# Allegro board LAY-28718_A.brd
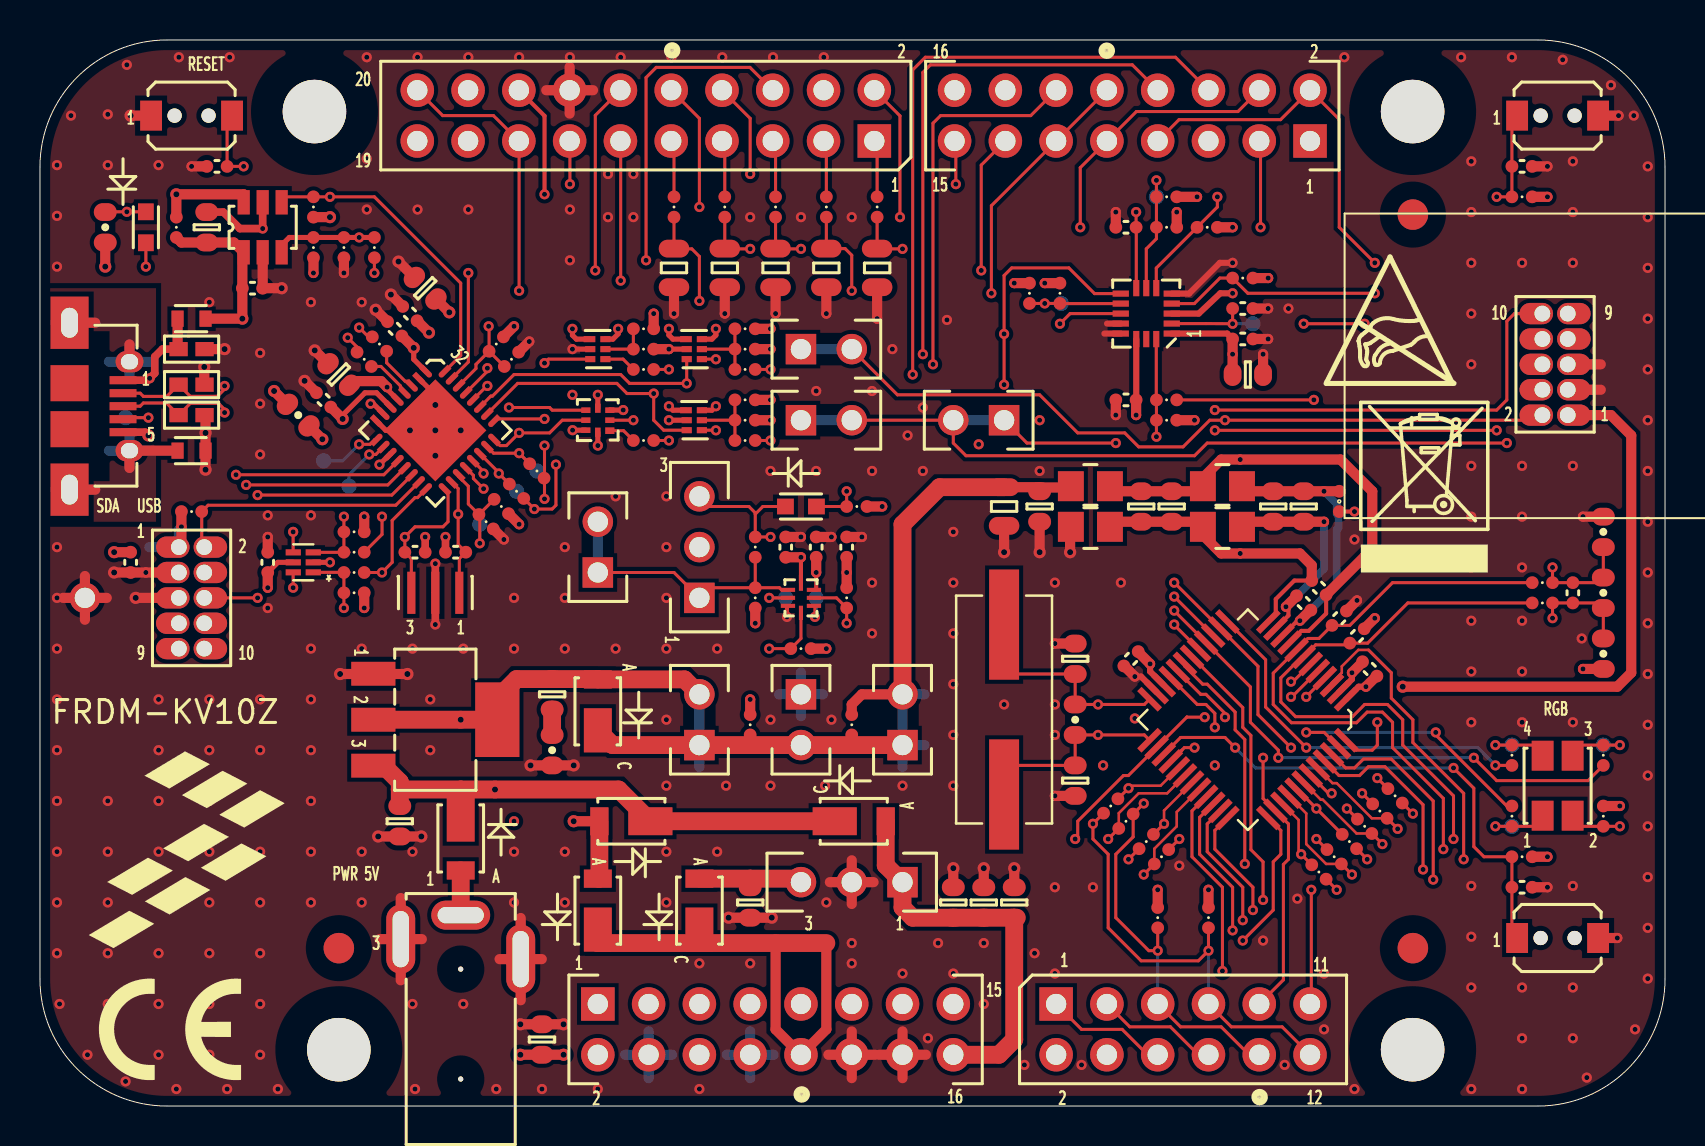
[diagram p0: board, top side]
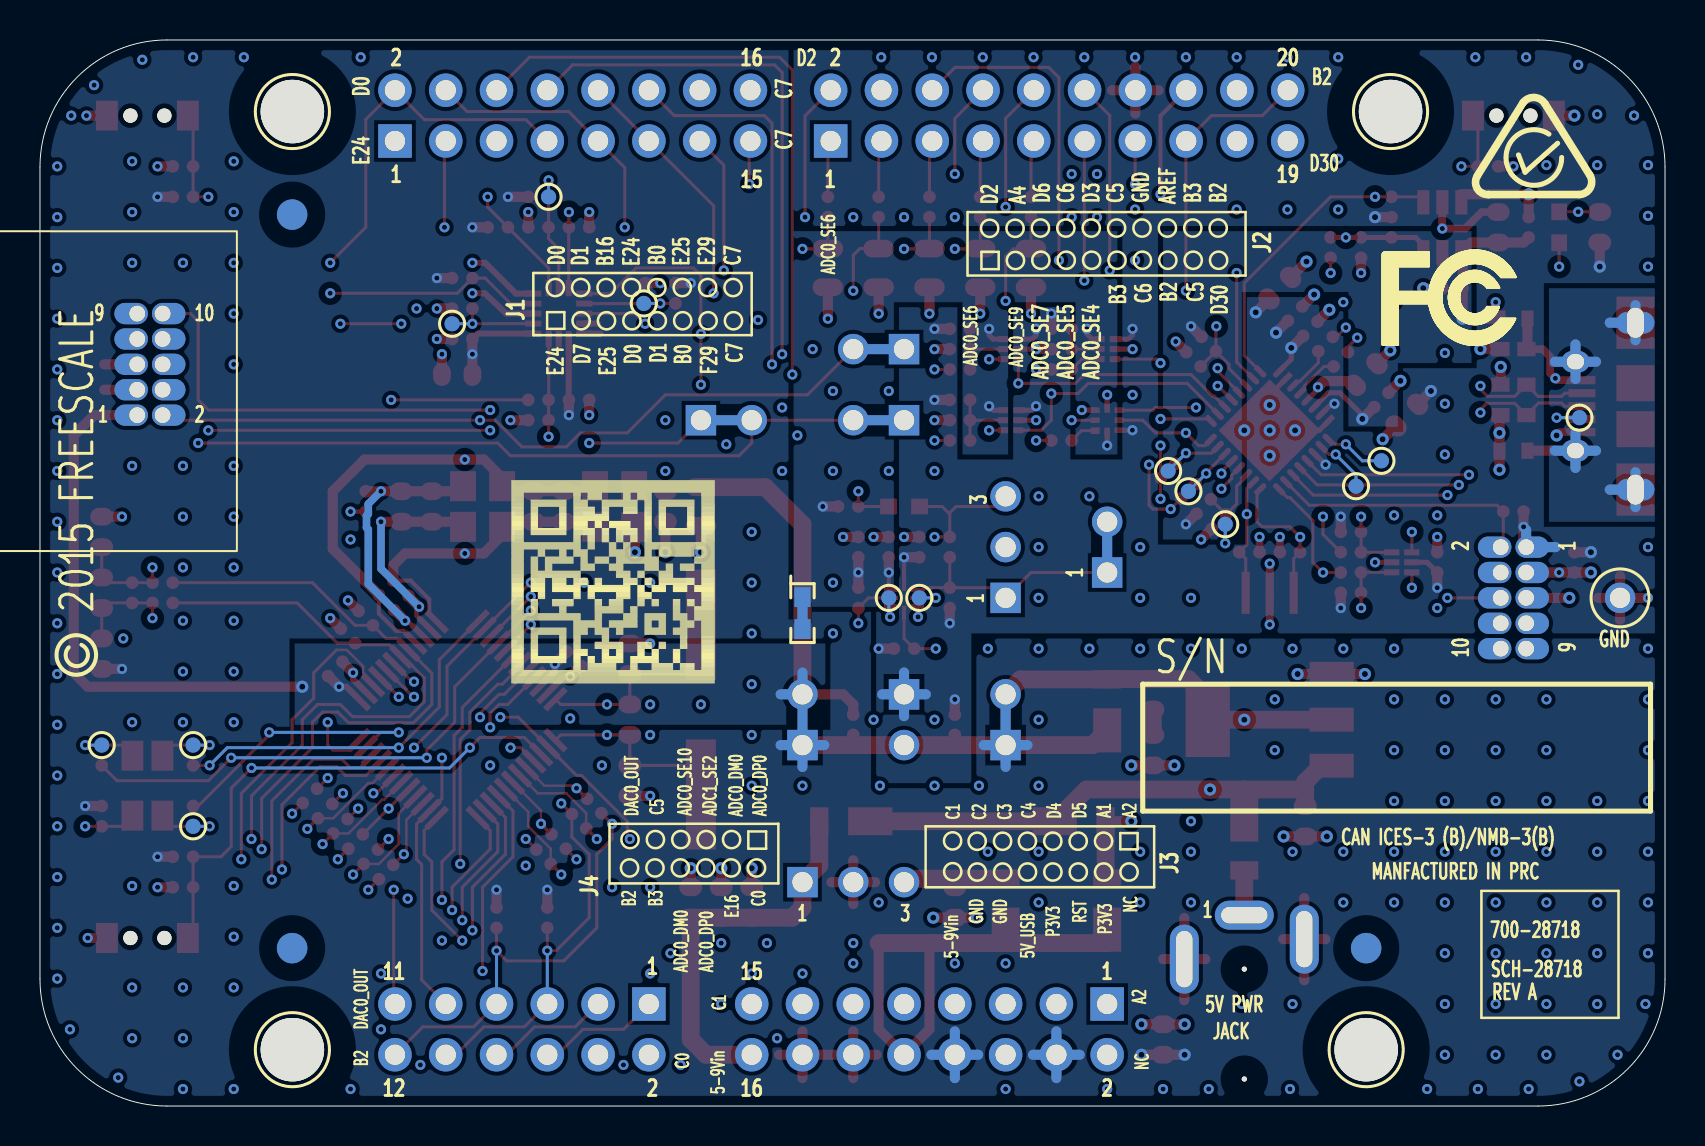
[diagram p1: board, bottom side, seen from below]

Outline 81.28 x 53.34 mm; copper layers: TOP, GND, INT_1, BOTTOM. Coordinates in mm from the lower left corner of the outline.
Outline path: 0,46.99 arc(1.86,51.48) 6.35,53.34 74.93,53.34 arc(79.42,51.48) 81.28,46.99 81.28,6.35 arc(79.42,1.86) 74.93,0 6.35,0 arc(1.86,1.86) 0,6.35 0,46.99

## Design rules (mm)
net group LEDRGB_BLUE: nets LEDRGB_BLUE PTE25
net group USB_SI_CONN_D: nets SDA_USB_CONN_DN SDA_USB_CONN_DP
net group USB_SI_D: nets SDA_USB_DN SDA_USB_DP

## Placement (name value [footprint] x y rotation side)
C1  10uF  [CC0402_25]  14.19 35.33 135 top
C2  1000pF  [CC0402_25]  8.85 47.02 180 top
C3  0.1UF  [CC0402_25]  60.16 39.9 0 top
C4  0.1UF  [CC0402_25]  60.16 38.38 0 top
C5  4.7uF  [CC0603_OV]  60.41 36.6 0 top
C6  22PF  [CC0402_25]  20.79 27.71 180 top
C7  0.1UF  [CC0402_25]  38.82 27.97 90 top
C8  0.1UF  [CC0402_25]  11.39 27.2 90 top
C9  22PF  [CC0402_25]  18.76 27.71 0 top
C10  0.1UF  [CC0402_25]  17.74 38.89 135 top
C11  2.2UF  [CC0603_OV]  14.95 36.6 135 top
C12  1.0UF  [CC0402_25]  18.5 39.65 135 top
C13  0.1UF  [CC0402_25]  54.32 43.97 180 top
C14  0.1UF  [CC0402_25]  54.32 35.33 180 top
C15  10uF  [CC0603_OV]  19.27 40.92 135 top
C16  0.1UF  [CC0402_25]  10.63 40.92 0 top
C17  4.7uF  [CC0402_25]  37.3 27.97 90 top
C18  0.1UF  [CC0402_25]  4.53 27.2 270 top
C19  18PF  [CC0603_OV]  8.34 43.97 90 top
C20  18PF  [CC0603_OV]  51.78 16.28 90 top
C21  0.1UF  [CC0402_25]  76.67 25.68 90 top
C22  2200PF  [CC0402_25]  65.87 23.52 45 top
C23  4.7uF  [CC0402_25]  40.35 27.97 90 top
C24  18PF  [CC0603_OV]  51.78 22.38 270 top
C29  0.1UF  [CC0402_25]  63.21 25.17 135 top
C30  0.1UF  [CC0402_25]  63.97 25.93 135 top
C31  0.1UF  [CC0402_25]  54.57 22.38 225 top
C32  0.1UF  [CC0402_25]  66.51 21.87 135 top
C33  0.1UF  [CC0603_OV]  50 30 270 top
C34  10UF  [CC0805_OV]  48.22 30 270 top
C35  2200PF  [CC0402_25]  64.99 24.41 45 top
C36  0.1UF  [CC0603_OV]  55.08 30 270 top
C39  0.1UF  [CC0603_OV]  56.6 30 270 top
C40  2.2UF  [CC0603_OV]  25.11 3.33 90 top
C41  10uF  [CC0603_OV]  18 14.25 270 top
C42  0.1UF  [CC0603_OV]  61.68 30 270 top
C43  0.1UF  [CC0603_OV]  63.21 30 270 top
C44  220PF  [CC0805_OV]  36.79 41.94 270 top
C50  10uF  [CC0603_OV]  48.73 10.19 90 top
C51  10uF  [CC0603_OV]  25.62 20.6 270 top
C52  10uF  [CC0603_OV]  47.21 10.19 90 top
C53  10uF  [CC0603_OV]  35.52 10.19 270 top
C54  10uF  [CC0603_OV]  45.68 10.19 90 top
C55  0.1UF  [CC0402_25]  74.13 10.95 0 top
C56  0.1UF  [CC0402_25]  74.13 47.02 0 top
C505  220PF  [CC0805_OV]  41.87 41.94 270 top
C507  220PF  [CC0805_OV]  34.25 41.94 270 top
C516  220PF  [CC0805_OV]  39.33 41.94 270 top
C522  220PF  [CC0805_OV]  31.71 41.94 270 top
D1  RED  [LED_0603]  38.06 30 180 top
D2  LED GREEN  [LED_0603]  5.3 43.97 270 top
D4  CLV1A-FKB-CJ1M1F1BB7R4S3  [LED4_3P4X3MM_SMT]  75.91 16.03 180 top
D5  DFLS130L-7  [POWERDI-123_3MMX2MM]  27.9 9.68 90 top
D6  DFLS130L-7  [POWERDI-123_3MMX2MM]  29.68 14.25 180 top
D9  DFLS130L-7  [POWERDI-123_3MMX2MM]  21.04 13.49 270 top
D10  DFLS130L-7  [POWERDI-123_3MMX2MM]  40.6 14.25 0 top
D11  DFLS130L-7  [POWERDI-123_3MMX2MM]  27.9 19.65 90 top
D13  DFLS130L-7  [POWERDI-123_3MMX2MM]  32.98 9.68 90 top
J1  CON_2X8  [HDR208_ESQ_SKT]  63.53 48.29 270 top
J2  CON_2x10  [HDR210_ESQ_SKT]  41.73 48.29 270 top
J3  CON_2X8  [HDR208_ESQ_SKT]  27.9 5.11 90 top
J4  CON_2X6  [HDR206_ESQ_SKT]  50.83 5.11 90 top
J5  HDR 1X2 TH  [SH_HDR102_BOTTOM]  27.9 26.7 180 top
J6  MICRO USB AB 5  [CON5_MICROUSB]  1.48 35.02 270 top
J8  HDR 1X2 TH  [SH_HDR102_BOTTOM]  38.06 34.32 90 top
J9  HDR 2X5  [HDR_5X2_FTSH_TH_NSP]  76.42 34.57 180 top
J10  HDR 2X5  [HDR_5X2_FTSH_TH_NSP]  6.95 27.97 0 top
J11  HDR 1X2 TH  [SH_HDR102_BOTTOM]  48.22 34.32 270 top
J12  HDR 1X2 TH  [SH_HDR102_BOTTOM]  38.06 37.87 90 top
J18  HDR 1X2  [HDR102]  38.06 20.6 0 top
J19  HDR 1X2 TH  [SH_HDR102_BOTTOM]  32.98 18.06 180 top
J20  HDR 1X2 TH  [SH_HDR102_BOTTOM]  43.14 18.06 180 top
J24  CON PWR 3  [CON_JACK_PJ1_022_TH-RA]  21.04 9.55 90 top
J25  HDR_1X3  [HDR103]  32.98 25.43 180 top
J27  HDR_1X3  [HDR103]  43.14 11.2 270 top
L1  330 OHM  [IND_1608]  7.58 32.79 0 top
L2  330 OHM  [IND_1608]  7.58 39.4 0 top
L3  1000@100MHZ  [IND_0805]  52.54 31.01 180 top
L8  1000@100MHZ  [IND_0805]  52.54 28.98 180 top
L9  1000@100MHZ  [IND_0805]  59.14 31.01 180 top
L10  1000@100MHZ  [IND_0805]  59.14 28.98 180 top
NOREF  -  []  66.07 28.85 0 top
NOREF#2  -  []  -239.61 -215.75 0 top
NOREF#3  -  []  -381.97 185.27 0 top
NOREF#4  -  []  -16.59 -36.7 0 top
NOREF#5  -  []  12.88 1.39 0 top
NOREF#6  -  []  2.44 7.9 0 top
NOREF#7  -  []  2.95 1.3 0 top
NOREF#8  -  []  0 41.47 0 top
NOREF#9  -  [unnamed#2]  68.67 7.9 0 top
NOREF#10  -  [unnamed#2]  14.95 7.9 0 top
NOREF#11  -  []  79.64 51.25 0 top
NOREF#12  -  []  64.35 36.16 0 top
NOREF#13  -  []  -408 -339.88 0 top
NOREF#14  -  [unnamed#2]  68.67 44.6 0 top
NOREF#15  -  []  192.91 64.47 0 top
NOREF#16  -  []  13.74 2.72 0 top
NOREF#17  -  []  70.32 0.01 90 top
NOREF#18  -  []  13.74 2.72 0 top
NOREF#19  -  [unnamed#2]  14.95 7.9 180 bottom
NOREF#20  -  [unnamed#2]  68.66 49.76 180 bottom
NOREF#21  -  []  6.57 47.46 180 bottom
NOREF#22  -  [unnamed#2]  13.73 49.76 180 bottom
NOREF#23  -  []  52.6 26.25 180 bottom
NOREF#24  -  [unnamed#2]  68.66 2.82 180 bottom
NOREF#25  -  [unnamed#2]  14.95 2.82 180 bottom
NOREF#26  -  []  26.12 14.76 180 bottom
NOREF#27  -  [unnamed#2]  68.67 44.6 180 bottom
NOREF#28  -  [unnamed#2]  68.67 7.9 180 bottom
NOREF#29  -  []  79.59 22.69 90 bottom
QZ1  10MHZ  [XTAL2-216X60-HCM49]  48.22 19.84 90 top
R1  10.0K  [RC0402_25]  74.13 45.49 180 top
R2  100  [RC0402_25]  40.86 30 180 top
R3  0  [RC0402_25]  24.85 31.78 135 top
R4  4.7K  [RC0402_25]  38.06 22.89 0 top
R5  4.7K  [RC0402_25]  23.08 30 135 top
R6  10.0K  [RC0402_25]  22.31 29.24 315 top
R7  10.0K  [RC0402_25]  23.58 37.36 45 top
R8  4.7K  [RC0402_25]  22.82 38.13 225 top
R9  10.0K  [RC0402_25]  60.16 41.43 180 top
R10  0  [RC0402_25]  35.78 27.97 90 top
R11  180K  [RC0402_25]  40.35 25.43 270 top
R12  4.7K  [RC0402_25]  35.27 35.33 180 top
R13  10.0K  [RC0402_25]  35.27 34.32 0 top
R14  10.0K  [RC0402_25]  35.78 25.43 90 top
R15  10.0K  [RC0402_25]  58.38 43.97 180 top
R16  10.0K  [RC0402_25]  30.19 37.87 0 top
R17  220  [RC0603_OV]  3.26 43.97 90 top
R18  0  [RC0402_25]  23.84 30.76 135 top
R19  0  [RC0402_25]  35.27 33.3 180 top
R20  33  [RC0402_25]  16.98 38.13 315 top
R21  10.0K  [RC0402_25]  7.58 29.74 0 top
R22  33  [RC0402_25]  16.22 37.36 315 top
R23  4.7K  [RC0402_25]  30.19 38.89 180 top
R24  0  [RC0402_25]  30.19 36.86 0 top
R25  0  [RC0402_25]  15.71 26.7 0 top
R26  10.0K  [RC0402_25]  15.71 25.68 180 top
R27  10.0K  [RC0402_25]  15.71 28.73 0 top
R28  0  [RC0402_25]  15.71 27.71 0 top
R29  1.0K  [RC0402_25]  16.73 42.95 90 top
R30  15K  [RC0402_25]  15.2 42.95 270 top
R31  10.0K  [RC0402_25]  56.35 43.97 0 top
R32  10.0K  [RC0402_25]  56.35 45.49 180 top
R33  0  [RC0402_25]  35.27 36.86 180 top
R34  10.0K  [RC0402_25]  13.68 42.95 90 top
R35  10.0K  [RC0402_25]  13.68 44.98 90 top
R36  0  [RC0603_OV]  12.92 34.57 315 top
R37  4.7K  [RC0402_25]  35.27 38.89 180 top
R38  0  [RC0402_25]  30.19 33.3 0 top
R39  10.0K  [RC0402_25]  35.27 37.87 0 top
R40  10.0K  [RC0402_25]  49.49 40.67 270 top
R41  0  [RC0402_25]  6.82 43.97 270 top
R42  10.0K  [RC0402_25]  56.35 34.32 0 top
R43  10.0K  [RC0402_25]  51.02 40.67 90 top
R44  4.99K  [RC0603_OV]  78.19 28.73 90 top
R45  4.99K  [RC0603_OV]  78.19 22.63 90 top
R46  100  [RC0402_25]  75.15 26.19 0 top
R47  100  [RC0402_25]  75.15 25.17 0 top
R48  4.99K  [RC0603_OV]  25.62 17.81 270 top
R49  10.0K  [RC0402_25]  55.91 9.42 270 top
R50  10.0K  [RC0402_25]  58.45 9.42 270 top
R52  1.0M  [RC0603_OV]  51.78 19.33 270 top
R53  0  [RC0402_25]  64.99 30.25 270 top
R54  0  [RC0402_25]  55.33 13.23 225 top
R55  0  [RC0402_25]  56.1 12.47 225 top
R58  0  [RC0402_25]  65.49 13.23 135 top
R59  0  [RC0402_25]  66.26 14 135 top
R60  0  [RC0402_25]  63.97 11.71 135 top
R61  0  [RC0402_25]  35.52 19.08 90 top
R62  0  [RC0402_25]  64.73 12.47 135 top
R63  10  [RC0402_25]  40.6 19.08 90 top
R64  0  [RC0402_25]  56.35 35.33 0 top
R65  0  [RC0402_25]  53.56 15.01 225 top
R66  0  [RC0402_25]  54.32 14.25 225 top
R67  0  [RC0402_25]  67.78 15.52 135 top
R68  0  [RC0402_25]  67.02 14.76 135 top
R69  576  [RC0402_25]  73.62 14.5 270 top
R73  270  [RC0402_25]  78.19 17.55 270 top
R74  270  [RC0402_25]  73.62 17.55 270 top
R75  10.0K  [RC0402_25]  74.13 12.47 180 top
R76  100  [RC0402_25]  36.79 44.98 90 top
R88  130  [RC0402_25]  78.19 14.5 270 top
R534  100  [RC0402_25]  41.87 44.98 90 top
R549  100  [RC0402_25]  39.33 44.98 90 top
R551  100  [RC0402_25]  34.25 44.98 90 top
R555  100  [RC0402_25]  31.71 44.98 90 top
RT1  10K  [RC0603_OV]  78.19 25.68 90 top
SH1  0  [SH0603]  43.14 24.66 270 bottom
SW1  SW2_STM151XX  [SW2_4X3MM_SM]  7.58 49.56 0 top
SW2  SW2_STM151XX  [SW2_4X3MM_SM]  75.91 49.56 0 top
SW3  SW2_STM151XX  [SW2_4X3MM_SM]  75.91 8.41 0 top
TP1  -  [TPAD_030]  24.85 31.78 180 bottom
TP2  -  [TPAD_030]  38.82 25.43 90 bottom
TP3  -  [TPAD_030]  37.3 25.43 90 bottom
TP4  -  [TPAD_030]  60.67 39.14 45 bottom
TP5  -  [TPAD_030]  22 29.11 180 bottom
TP6  -  [TPAD_030]  23.84 30.76 180 bottom
TP7  -  [TPAD_030]  4.28 34.44 180 bottom
TP8  -  [TPAD_030]  55.84 45.49 315 bottom
TP9  -  [TPAD_030]  15.46 31.01 180 bottom
TP10  -  [TPAD_030]  14.19 32.28 180 bottom
TP11  -  [TPAD_030]  51.08 40.16 45 bottom
TP13  -  [TPAD_030]  73.62 14 270 bottom
TP14  -  [TPAD_030]  78.19 18.06 270 bottom
TP16  TEST POINT WHITE  [TEST_LOOP]  2.25 25.43 180 bottom
TP17  -  [TPAD_030]  73.62 18.06 270 bottom
U1  0402ESDA-MLP  [0402_MLP]  7.58 37.87 0 top
U2  74LVCH1T45  [UDFN6_1X1P5MM]  32.73 34.32 0 top
U3  NTSX2102GU8H  [XQFN8_1P45X1P25MM]  38.06 25.43 270 top
U4  0402ESDA-MLP  [0402_MLP]  7.58 36.09 0 top
U5  MK20DX128VFM5  [QFN32_S142EP]  19.77 33.81 315 top
U6  0402ESDA-MLP  [0402_MLP]  7.58 34.57 0 top
U7  74LVCH1T45  [UDFN6_1X1P5MM]  27.9 37.87 0 top
U8  FXOS8700CQ  [QFN5X3_0P5_3X3]  55.33 39.65 180 top
U9  NLX2G14  [UDFN6_1P45X1_0P5MM]  13.17 27.2 180 top
U10  74LVC2T45GM,125  [QFN8_1P6X1P6MM]  27.9 34.32 180 top
U11  MIC2005-0.8YM6  [SOT23-6_A]  11.14 43.97 90 top
U12  74LVCH1T45  [UDFN6_1X1P5MM]  32.73 37.87 0 top
U13  MKV10Z32VLF7  [QFP50P900X900X160-48N]  60.41 19.33 225 top
U17  NCP1117ST33T3G  [SOT223]  19.77 19.33 270 top
Y1  8.00MHZ  [XTAL3_3P35X1P45_SM]  19.77 25.68 0 top

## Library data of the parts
C1-C6 C9 C11-C14 C21 C22 C29-C32 C35 C40 C41 C44 C50-C56 C505 C507 C516 C522 = CAP_NP
C7 C8 C10 C15-C18 C23 C33 C34 C36 C39 C42 C43 = CAP_NP: tolerance: 10%
C19 C20 C24 = CAP_NP: tolerance: 5%
D1 D2 = LED
D4 = CLV1A_LED_4P
D5 D6 D9-D11 D13 = DIODE_SCHTKY
J1 J3 = CONN_HDR_8X2
J2 = CONN_HDR_10X2
J4 = CONN_HDR_6X2
J5 J8 J11 J12 J18-J20 = CONN_HDR_2X1
J6 = USB_MINI_AB_RECEPTACLE
J9 J10 = CONN_HDR_5X2
J24 = DC POWER JACK
J25 J27 = CONN_HDR_3X1
L1 L2 = BEAD
L3 L8-L10 = INDUCTOR_FERRITE: tolerance: 25%
QZ1 = CRYSTAL
R1 R2 R4 R5 R8 R9 R12 R15 R23 R29 R30 R34 R35 R37 R49 R50 R54 R55 R58-R60 R62 R65-R68 R75 R76 R534 R549 R551 R555 = RES: tolerance: 1%
R3 R6 R7 R11 R17-R22 R25 R28 R31-R33 R36 R40-R48 R53 R61 R63 R64 R69 R74 R88 = RES
R10 R13 R14 R16 R24 R26 R27 R38 R39 R52 = RES: tolerance: 5%
R73 = RES: signal model: DEFAULT_RESISTOR_330.000000OHM_2_1
RT1 = THERMISTOR
SH1 = RES_SHORT-2
SW1-SW3 = SW2_STM151XX
TP1-TP11 TP13 TP14 TP16 TP17 = TestLoop
U1 U4 U6 = DIODE_TVS_BIDIR
U2 U7 U12 = 74LVCH1T45_6P
U3 = NTSX2102GU8H_8P
U5 = PK20DX128V_QFN_32P
U8 = FXOS8700CQ_QFN_16P
U9 = NLU2GU04
U10 = 74LVC2T45GM_8P
U11 = MIC2005-0.8YM6
U13 = MKV10Z32VLF7_LQFP48_6
U17 = LD1117AS18
Y1 = XTAL_CS

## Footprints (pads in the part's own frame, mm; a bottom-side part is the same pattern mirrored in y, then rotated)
0402_MLP
  rect 0.914x0.711 smd: 1(-0.65,0) 2(0.65,0)
CC0402_25
  round 0.635 smd: 1(-0.508,0) 2(0.508,0)
CC0603_OV
  oval 0.889x1.143 smd: 1(-0.762,0) 2(0.762,0)
CC0805_OV
  oval 0.889x1.524 smd: 1(-0.965,0) 2(0.965,0)
CON5_MICROUSB
  rect 1.803x1.905 smd: (-1.15,0) (1.15,0)
  rect 0.406x1.346 smd: 1(-1.3,2.675) 2(-0.65,2.675) 3(0,2.675) 4(0.65,2.675) 5(1.3,2.675)
  oval 1.067x1.397 hole 0.762x0.864: S1(-2.225,3) S2(2.225,3)
  rect 2.616x1.905 hole 1.499x0.838: S3(-4.175,0) S4(4.175,0)
CON_JACK_PJ1_022_TH-RA
  round 0.254 hole 1.6 unplated: (-8.2,0) (-2.7,0)
  oval 1.448x2.946 hole 0.813x2.311: 1(0,0)
  oval 3.454x1.448 hole 2.819x0.813: 2(-2.2,-3) 3(-1.2,3)
HDR102
  rect 1.524x1.524 hole 1.016: 1(0,0)
  round 1.524 hole 1.016: 2(0,-2.54)
HDR103
  rect 1.524x1.524 hole 1.016: 1(0,0)
  round 1.524 hole 1.016: 2(0,-2.54) 3(0,-5.08)
HDR206_ESQ_SKT
  rect 1.676x1.676 hole 1.016: 1(0,0)
  round 1.676 hole 1.016: 2(-2.54,0) 3(0,-2.54) 4(-2.54,-2.54) 5(0,-5.08) 6(-2.54,-5.08) 7(0,-7.62) 8(-2.54,-7.62) 9(0,-10.16) 10(-2.54,-10.16) 11(0,-12.7) 12(-2.54,-12.7)
HDR208_ESQ_SKT
  rect 1.676x1.676 hole 1.016: 1(0,0)
  round 1.676 hole 1.016: 2(-2.54,0) 3(0,-2.54) 4(-2.54,-2.54) 5(0,-5.08) 6(-2.54,-5.08) 7(0,-7.62) 8(-2.54,-7.62) 9(0,-10.16) 10(-2.54,-10.16) 11(0,-12.7) 12(-2.54,-12.7) 13(0,-15.24) 14(-2.54,-15.24) 15(0,-17.78) 16(-2.54,-17.78)
HDR210_ESQ_SKT
  rect 1.676x1.676 hole 1.016: 1(0,0)
  round 1.676 hole 1.016: 2(-2.54,0) 3(0,-2.54) 4(-2.54,-2.54) 5(0,-5.08) 6(-2.54,-5.08) 7(0,-7.62) 8(-2.54,-7.62) 9(0,-10.16) 10(-2.54,-10.16) 11(0,-12.7) 12(-2.54,-12.7) 13(0,-15.24) 14(-2.54,-15.24) 15(0,-17.78) 16(-2.54,-17.78) 17(0,-20.32) 18(-2.54,-20.32) 19(0,-22.86) 20(-2.54,-22.86)
HDR_5X2_FTSH_TH_NSP
  oval 1.676x1.067 hole 0.787: 1(0,0) 2(1.27,0) 3(0,-1.27) 4(1.27,-1.27) 5(0,-2.54) 6(1.27,-2.54) 7(0,-3.81) 8(1.27,-3.81) 9(0,-5.08) 10(1.27,-5.08)
IND_0805
  rect 1.295x1.499 smd: 1(-0.978,0) 2(0.978,0)
IND_1608
  rect 0.61x0.813 smd: 1(-0.7,0) 2(0.7,0)
LED4_3P4X3MM_SMT
  rect 1.092x1.499 smd: 1(0.75,1.5) 2(-0.75,1.5) 3(-0.75,-1.5) 4(0.75,-1.5)
LED_0603
  rect 0.838x0.787 smd: A(-0.775,0) C(0.775,0)
POWERDI-123_3MMX2MM
  rect 0.914x1.397 smd: A(1.7,0)
  rect 2.21x1.397 smd: C(-0.85,0)
QFN5X3_0P5_3X3
  rect 0.813x0.305 smd: 1(-1.275,1) 2(-1.275,0.5) 3(-1.275,0) 4(-1.275,-0.5) 5(-1.275,-1) 9(1.275,-1) 10(1.275,-0.5) 11(1.275,0) 12(1.275,0.5) 13(1.275,1)
  rect 0.305x0.813 smd: 6(-0.5,-1.275) 7(0,-1.275) 8(0.5,-1.275) 14(0.5,1.275) 15(0,1.275) 16(-0.5,1.275)
QFN8_1P6X1P6MM
  rect 0.457x0.33 smd: 1(-0.6,0.525)
  rect 0.457x0.279 smd: 2(-0.6,0) 3(-0.6,-0.5) 5(0.6,-0.5) 6(0.6,0) 7(0.6,0.5)
  rect 0.279x0.457 smd: 4(0,-0.6) 8(0,0.6)
QFN32_S142EP
  custom 0.07x0.07 smd: 1(-2.4,1.751) 2(-2.4,1.251) 3(-2.4,0.751) 4(-2.4,0.25) 5(-2.4,-0.25) 6(-2.4,-0.751) 7(-2.4,-1.251) 8(-2.4,-1.751) 9(-1.751,-2.4) 10(-1.251,-2.4) 11(-0.751,-2.4) 12(-0.25,-2.4) 13(0.25,-2.4) 14(0.751,-2.4) 15(1.251,-2.4) 16(1.751,-2.4) 17(2.4,-1.751) 18(2.4,-1.251) 19(2.4,-0.751) 20(2.4,-0.25) 21(2.4,0.25) 22(2.4,0.751) 23(2.4,1.251) 24(2.4,1.751) 25(1.751,2.4) 26(1.251,2.4) 27(0.751,2.4) 28(0.25,2.4) 29(-0.25,2.4) 30(-0.751,2.4) 31(-1.251,2.4) 32(-1.751,2.4)
  rect 3.607x3.607 smd: 33(0,0)
QFP50P900X900X160-48N
  rect 1.448x0.305 smd: 1(-4.2,2.75) 2(-4.2,2.25) 3(-4.2,1.75) 4(-4.2,1.25) 5(-4.2,0.75) 6(-4.2,0.25) 7(-4.2,-0.25) 8(-4.2,-0.75) 9(-4.2,-1.25) 10(-4.2,-1.75) 11(-4.2,-2.25) 12(-4.2,-2.75) 25(4.2,-2.75) 26(4.2,-2.25) 27(4.2,-1.75) 28(4.2,-1.25) 29(4.2,-0.75) 30(4.2,-0.25) 31(4.2,0.25) 32(4.2,0.75) 33(4.2,1.25) 34(4.2,1.75) 35(4.2,2.25) 36(4.2,2.75)
  rect 0.305x1.448 smd: 13(-2.75,-4.2) 14(-2.25,-4.2) 15(-1.75,-4.2) 16(-1.25,-4.2) 17(-0.75,-4.2) 18(-0.25,-4.2) 19(0.25,-4.2) 20(0.75,-4.2) 21(1.25,-4.2) 22(1.75,-4.2) 23(2.25,-4.2) 24(2.75,-4.2) 37(2.75,4.2) 38(2.25,4.2) 39(1.75,4.2) 40(1.25,4.2) 41(0.75,4.2) 42(0.25,4.2) 43(-0.25,4.2) 44(-0.75,4.2) 45(-1.25,4.2) 46(-1.75,4.2) 47(-2.25,4.2) 48(-2.75,4.2)
RC0402_25
  round 0.635 smd: 1(-0.508,0) 2(0.508,0)
RC0603_OV
  oval 0.889x1.143 smd: 1(-0.762,0) 2(0.762,0)
SH0603
  rect 0.991x0.813 smd: 1(-0.8,0) 2(0.8,0)
SH_HDR102_BOTTOM
  rect 1.524x1.524 hole 1.016: 1(0,0)
  round 1.524 hole 1.016: 2(0,-2.54)
SOT23-6_A
  rect 1.219x0.61 smd: 1(-1.25,0.95) 2(-1.25,0) 3(-1.25,-0.95) 4(1.25,-0.95) 5(1.25,0) 6(1.25,0.95)
SOT223
  rect 1.194x2.21 smd: 1(-2.3,-3.1) 2(0,-3.1) 3(2.3,-3.1)
  rect 3.734x2.21 smd: 4(0,3.1)
SW2_4X3MM_SM
  round 0.711 hole 0.711 unplated: (-0.85,0) (0.85,0)
  rect 1.092x1.499 smd: 1(-2.025,0) 2(2.025,0)
TEST_LOOP
  round 1.524 hole 1.016: 1(0,0)
TPAD_030
  round 0.762 smd: 1(0,0)
UDFN6_1P45X1_0P5MM
  rect 0.762x0.305 smd: 1(-0.5,0.5) 2(-0.5,0) 3(-0.5,-0.5) 4(0.5,-0.5) 5(0.5,0) 6(0.5,0.5)
UDFN6_1X1P5MM
  rect 0.584x0.305 smd: 1(-0.418,0.5)
  rect 0.508x0.305 smd: 2(-0.38,0) 3(-0.38,-0.5) 4(0.38,-0.5) 5(0.38,0) 6(0.38,0.5)
unnamed#2
  round 1.524 smd: (0,0)
XQFN8_1P45X1P25MM
  rect 0.787x0.203 smd: 1(-0.75,0)
  rect 0.203x0.711 smd: 2(-0.4,-0.65) 3(0,-0.65) 4(0.4,-0.65) 6(0.4,0.65) 7(0,0.65) 8(-0.4,0.65)
  rect 0.711x0.203 smd: 5(0.75,0)
XTAL2-216X60-HCM49
  rect 5.512x1.499 smd: 1(-4.25,0) 2(4.25,0)
XTAL3_3P35X1P45_SM
  rect 0.406x2.108 smd: 1(1.2,0) 2(0,0) 3(-1.2,0)

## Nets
GND: C1.2 C2.2 C3.2 C4.2 C5.2 C6.2 C7.2 C8.2 C9.2 C10.2 C11.2 C12.2 C13.2 C14.2 C15.2 C16.2 C17.2 C18.2 C20.1 C22.2 C23.2 C24.1 C31.2 C32.2 C33.2 C34.2 C35.2 C40.2 C41.2 C44.2 C50.2 C52.2 C53.2 C54.2 C55.2 C56.2 C505.2 C507.2 C516.2 C522.2 J2.14 J3.12(B6) J3.14(B7) J6.5(P5) J9.3(A2) J9.5(A3) J10.3(A2) J10.5(A3) J24.2 J24.3 J27.2 L1.2 L8.2 R6.2 R7.2 R13.2 R16.2 R30.2 R31.2 R39.2 R42.2 R43.2 R44.2 R48.2 SW1.1(SW1) SW2.2(SW2) SW3.2(SW2) TP16.1(PIN1) U1.2(A2) U2.2(GND) U3.4(GND) U4.2(A2) U5.2(VSS1) U5.8(VSSA) U5.33(EPAD) U6.2(A2) U7.2(GND) U8.3(RSVD1) U8.5(GND1) U8.12(GND2) U8.13(RSVD2) U9.2(GND) U10.3(DIR) U10.4(GND) U11.2(GND) U12.2(GND) U13.2(VSS_2) U13.23(VSS_23) U17.1(GND) Y1.2
P3V3: C4.1 C5.1 C14.1 C40.1 D11.C J3.4(B2) J3.8(B4) J18.2 J19.1 J20.1 R1.1 R9.1 R15.1 R32.1 R40.1 R45.1 R49.1 R50.1 R61.1 R63.1 R75.1 R88.1 SH1.2 U8.1(VDDIO) U8.14(VDD)
P3V3_KV10: C31.1 C32.1 C33.1 C34.1 J9.1(A1) J20.2 L3.2 R63.2 U13.1(VDD_1) U13.22(VDD_22)
P3V3_SDA: C8.1 C10.1 C12.1 C15.1 C17.1 C18.1 J10.1(A1) J18.1 R4.2 R12.1 R14.1 R17.1 R21.1 R23.1 R26.1 R27.2 R35.1 R36.1 R37.1 R61.2 U2.1(VCCA) U3.1(VCCA) U5.1(VDD1) U5.7(VDDA) U5.11(VBAT) U7.1(VCCA) U9.5(VCC) U10.7(VCCA) U12.1(VCCA)
P3V3_VREG: C51.1 D11.A J19.2 U17.2(VOUT) U17.4(TAB)
P5V0_SDA_USB_CONN_VBUS: J6.1(P1) L2.1 U1.1(A1)
P5V_OPT_VR: C53.1 D13.A J27.3
P5V_SDA: C1.1 C16.1 C19.1 L2.2 R5.1 R8.1 R34.1 R41.2 U5.6(VREGIN) U11.1(VIN)
P5V_SDA_PSW: D5.A D6.A R41.1 U11.6(VOUT)
P5V_USB: D5.C D13.C J3.10(B5)
VDDA: C30.1 C36.1 C39.1 L3.1 L9.2 U13.9(VDDA)
VSSA: C30.2 C36.2 C39.2 L8.1 L10.2 U13.12(VSSA)
ADC0_DM0: C35.1 J4.3(A2) J4.8(B4) R46.1 U13.8(ADC0_SE4/ADC0_DM0/PTE21/FTM1_CH1/UART0_RX)
ADC0_DP0: C22.1 J4.1(A1) J4.6(B3) R47.1 U13.7(ADC0_SE0/ADC0_DP0/PTE20/FTM1_CH0/UART0_TX)
ADC0_SE5/PTE17: C507.1 R551.1 U13.4(ADC0_SE5/ADC1_SE5/ADC0_DM1/PTE17/SPI0_SCK/UART1_RX/FTM_CLKIN1/LPTMR0_ALT3)
ADC0_SE5_RC: J2.7 R551.2
ADC0_SE6/PTE18: C505.1 R534.1 U13.5(ADC0_SE6/ADC1_SE1/ADC1_DP1/PTE18/SPI0_SOUT/UART1_CTS_B/I2C0_SDA/SPI0_SIN)
ADC0_SE6_RC: J2.1 R534.2
ADC0_SE7/PTE19: C44.1 R76.1 U13.6(ADC0_SE7/ADC1_SE7/ADC1_DM1/PTE19/SPI0_SIN/UART1_RTS_B/I2C0_SCL/SPI0_SOUT)
ADC0_SE7_RC: J2.5 R76.2
ADC0_SE9/PTB1: C516.1 R549.1 U13.28(ADC0_SE9/ADC1_SE9/PTB1/EWM_IN/FTM0_FLT2/I2C0_SDA/FTM1_CH1/FTM1_QD_PHB/UART0_TX)
ADC0_SE9_RC: J2.3 R549.2
ADC1_SE4/PTE30: C522.1 J4.11(A6) R555.1 U13.14(ADC1_SE4/CMP0_IN4/CMP1_IN4/DAC0_OUT/PTE30/FTM0_CH3/FTM_CLKIN1)
ADC1_SE4_RC: J2.9 R555.2
AREF: J2.16 R53.2
DC_JACK: D9.A J24.1(PIN)
FXOS8700CQ_CRST: C13.1 U8.8(CRST)
FXOS8700CQ_I2C_SA0: R31.1 R32.2 TP8.1(PIN1) U8.7(SA0/MISO)
FXOS8700CQ_I2C_SA1: R40.2 R43.1 TP11.1(PIN1) U8.10(SA1/C\S\)
LEDRGB_BLUE: D4.3(BLUE_C) R73.1 TP14.1(PIN1)
LEDRGB_GREEN: D4.4(GREEN_C) R74.1 TP17.1(PIN1)
LEDRGB_RED: D4.1(RED_C) R69.2 TP13.1(PIN1)
LVLRST_EN: R4.1 U3.5(OE)
MMA8451_BYP: C3.1 TP4.1(PIN1) U8.2(BYP)
P5-9V_VIN: C50.1 C52.1 C54.1 D10.A J3.16(B8) J27.1
P5-9V_VIN_VR: C41.1 D6.C D9.C D10.C U17.3(VIN)
POWER_EN: R29.1 U5.31(ADC0_SE7B/PTD6/SPI0_PCS3/UART0_RX/FTM0_CH6/FTM0_FLT0/LLWU_P15)
PTA1/FTM2_CH0: J3.3(A2) U13.18(PTA1/UART0_RX/FTM2_CH0/CMP0_OUT/FTM2_QD_PHA/FTM1_CH1)
PTA2/FTM2_CH1: J3.1(A1) U13.19(PTA2/UART0_TX/FTM2_CH1/CMP1_OUT/FTM2_QD_PHB/FTM1_CH0)
PTA4: C56.1 J2.4 R1.2 SW2.1(SW1) U13.21(PTA4/LLWU_P3/FTM0_CH1/FTM0_FLT3/NMI_B)
PTB0: C55.1 J1.10(B5) J1.11(A6) R75.2 SW3.1(SW1) U13.27(ADC0_SE8/ADC1_SE8/PTB0/LLWU_P5/I2C0_SCL/FTM1_CH0/FTM1_QD_PHA/UART0_RX)
PTB2: J2.15 J2.20 J4.7(A4) J4.12(B6) R50.2 R65.2 U8.9(INT2)
PTB3: J2.11 J2.18 J4.5(A3) J4.10(B5) R49.2 R66.1 U8.11(INT1)
PTC0: J4.2(B1) U13.33(ADC1_SE11/PTC0/SPI0_PCS4/PDB0_EXTRG/CMP0_OUT/FTM0_FLT0/SPI0_PCS0/SS_B)
PTC1/FTM0_CH0: J3.15(A8) U13.34(ADC1_SE3/PTC1/LLWU_P6/SPI0_PCS3/UART1_RTS_B/FTM0_CH0/FTM2_CH0)
PTC2/FTM0_CH1: J3.13(A7) U13.35(ADC0_SE11/CMP1_IN0/PTC2/SPI0_PCS2/UART1_CTS_B/FTM0_CH1/FTM2_CH1)
PTC3/FTM0_CH2: J3.11(A6) U13.36(CMP1_IN1/PTC3/LLWU_P7/SPI0_PCS1/UART1_RX/FTM0_CH2/CLKOUT)
PTC4/FTM0_CH3: J3.9(A5) U13.37(PTC4/LLWU_P8/SPI0_PCS0/SS_B/UART1_TX/FTM0_CH3/CMP1_OUT)
PTC5: J2.12 J2.17 J4.9(A5) U13.38(PTC5/LLWU_P9/SPI0_SCK/LPTMR0_ALT2/FTM0_CH2/CMP0_OUT)
PTC6: J2.13 R60.2 R67.2 U13.39(CMP0_IN0/PTC6/LLWU_P10/SPI0_SOUT/PDB0_EXTRG/UART0_RX/I2C0_SCL)
PTC6/I2C0_SCL: R9.2 R60.1 U8.4(SCL/SCLK)
PTC6/SPI0_SOUT: J2.8 R67.1
PTC7: J1.15(A8) J1.16(B8) R62.1 U13.40(CMP0_IN1/PTC7/SPI0_SIN/UART0_TX/I2C0_SDA)
PTC7/I2C0_SDA: R15.2 R62.2 U8.6(SDA/MOSI)
PTD0: J1.2(B1) J1.7(A4) R58.1
PTD1: J1.4(B2) J1.9(A5) R59.2 R64.2
PTD2: J2.2 U13.43(PTD2/LLWU_P13/SPI0_SOUT/UART0_RX/FTM0_CH2/I2C0_SCL)
PTD3: J2.19 R68.1 U13.44(PTD3/SPI0_SIN/UART0_TX/FTM0_CH3/I2C0_SDA)
PTD3/SPI0_SIN: J2.10 R68.2
PTD4/FTM0_CH4: J3.7(A4) U13.45(PTD4/LLWU_P14/SPI0_PCS1/UART0_RTS_B/FTM0_CH4/FTM2_CH0/EWM_IN)
PTD5/FTM0_CH5: J3.5(A3) U13.46(ADC0_SE3/PTD5/SPI0_PCS2/UART0_CTS_B/FTM0_CH5/FTM2_CH1/EWM_OUT_B)
PTD6: J2.6 R69.1 U13.47(ADC1_SE6/PTD6/LLWU_P15/SPI0_PCS3/UART0_RX/FTM0_CH0/FTM1_CH0/FTM0_FLT0)
PTD7: J1.3(A2) U13.48(PTD7/UART0_TX/FTM0_CH1/FTM1_CH1/FTM0_FLT1)
PTE16: J4.4(B2) U13.3(ADC0_SE1/ADC0_DP1/ADC1_SE0/PTE16/SPI0_PCS0/SS_B/UART1_TX/FTM_CLKIN0/FTM0_FLT3)
PTE24: J1.1(A1) J1.8(B4) U13.15(PTE24/FTM0_CH0/I2C0_SCL/EWM_OUT_B)
PTE25: J1.5(A3) J1.12(B6) R73.2 U13.16(PTE25/FTM0_CH1/I2C0_SDA/EWM_IN)
PTE29: J1.13(A7) J1.14(B7) R74.2 U13.13(CMP1_IN5/CMP0_IN5/PTE29/FTM0_CH2/FTM_CLKIN0)
RST_TGTMCU_B: D1.C(CATHODE) J3.6(B3) J9.10(B5) J25.3 R10.2 R11.2 U3.7(B1) U13.26(PTA20/RESET_B)
SDA_EXTAL: C9.1 U5.17(EXTAL0/PTA18/FTM0_FLT2/FTM_CLKIN0) Y1.3
SDA_JTAG_TCLK: J10.4(B2) U5.12(JTAG_TCLK/SWD_CLK/EZP_CLK/TSI0_CH1/PTA0/U\A\R\T\0\_\C\T\S\/U\A\R\T\0\_\C\O\L\/FTM0_CH5)
SDA_JTAG_TDI: J10.8(B4) U5.13(JTAG_TDI/EZP_DI/TSI0_CH2/PTA1/UART0_RX/FTM0_CH6)
SDA_JTAG_TDO: J10.6(B3) U5.14(JTAG_TDO/TRACE_SWO/EZP_DO/TSI0_CH3/PTA2/UART0_TX/FTM0_CH7)
SDA_JTAG_TMS: J10.2(B1) R21.2 U5.15(JTAG_TMS/SWD_DIO/TSI0_CH4/PTA3/U\A\R\T\0\_\R\T\S\/FTM0_CH0)
SDA_LED: D2.C(CATHODE) U5.29(PTD4/SPI0_PCS1/U\A\R\T\0\_\R\T\S\/FTM0_CH4/EWM_IN/LLWU_P14)
SDA_LED_R: D2.A(ANODE) R17.2
SDA_RST: J10.10(B5) R5.2 R6.1 TP5.1(PIN1) U5.19(R\E\S\E\T\)
SDA_RST_LED: D1.A(ANODE) R2.2
SDA_RST_TGTMCU_B: J5.2 U5.21(ADC0_SE9/TSI0_CH6/PTB1/I2C0_SDA/FTM1_CH1/FTM1_QD_PHB)
SDA_RST_TGTMCU_J_B: J5.1 J25.1 R10.1 R14.2 U3.2(A1)
SDA_RX_EN: R16.1 R23.2 U7.5(DIR)
SDA_SPI0_CS: R3.2 TP1.1(PIN1) U5.23(ADC0_SE4B/CMP1_IN0/TSI0_CH15/PTC2/SPI0_PCS2/U\A\R\T\1\_\C\T\S\/FTM0_CH1/I2S0_TX_FS)
SDA_SPI0_RST_B: R18.2 TP6.1(PIN1) U5.22(ADC0_SE15/TSI0_CH14/PTC1/SPI0_PCS3/U\A\R\T\1\_\R\T\S\/FTM0_CH0/I2S0_TXD0/LLWU_P6)
SDA_SPI0_SCK: U2.3(A) U5.26(PTC5/SPI0_SCK/LPTMR0_ALT2/I2S0_RXD0/CMP0_OUT/LLWU_P9)
SDA_SPI0_SIN: U5.28(CMP0_IN1/PTC7/SPI0_SIN/USB_SOF_OUT/I2S0_RX_FS) U10.5(2A)
SDA_SPI0_SOUT: U5.27(CMP0_IN0/PTC6/SPI0_SOUT/PDB0_EXTRG/I2S0_RX_BCLK/I2S0_MCLK/LLWU_P10) U12.3(A)
SDA_SWD_EN: R18.1 R19.1 U9.6(Y\2\)
SDA_SWD_EN_B: R25.2 U5.16(N\M\I\/E\Z\P\_\C\S\/TSI0_CH5/PTA4/FTM0_CH1/LLWU_P3)
SDA_SWD_EN_B_R: R25.1 R26.2 U9.1(A1)
SDA_SWD_EN_R: R12.2 R13.1 R19.2 U2.5(DIR)
SDA_SWD_OE: R3.1 R33.1 U9.4(Y\1\)
SDA_SWD_OE_B: R28.2 U5.20(ADC0_SE8/TSI0_CH0/PTB0/I2C0_SCL/FTM1_CH0/FTM1_QD_PHA/LLWU_P5)
SDA_SWD_OE_B_R: R27.1 R28.1 U9.3(A2)
SDA_SWD_OE_R: R33.2 R37.2 R39.1 U12.5(DIR)
SDA_USB_CONN_DN: J6.2(P2) R22.1 U4.1(A1)
SDA_USB_CONN_DP: J6.3(P3) R20.1 U6.1(A1)
SDA_USB_DN: R22.2 U5.4(USB0_DM)
SDA_USB_DP: R20.2 U5.3(USB0_DP)
SDA_USB_P5V_SENSE: R7.1 R8.2 U5.30(ADC0_SE6B/PTD5/SPI0_PCS2/U\A\R\T\0\_\C\T\S\/U\A\R\T\0\_\C\O\L\/FTM0_CH5/E\W\M\_\O\U\T\)
SDA_USBSHIELD: J6.S1(SHLD1) J6.S2(SHLD2) J6.S3(SHLD3) J6.S4(SHLD4) L1.1
SDA_VOUT33: C11.1 R36.2 U5.5(VOUT33)
SDA_XTAL: C6.1 U5.18(XTAL0/PTA19/FTM1_FLT0/FTM_CLKIN1/LPTMR0_ALT1) Y1.1
SW1_RST_B: C2.1 J25.2 SW1.2(SW2)
SWD_CLK_KV10: J11.1 U13.17(PTA0/UART0_CTS_B/FTM0_CH5/SWD_CLK)
SWD_CLK_TGTMCU: J8.2 J9.4(B2) J11.2
SWD_CLK_TGTMCU_BUF: J8.1 U2.4(B)
SWD_DIO_TGTMCU: J9.2(B1) J12.2 U13.20(PTA3/UART0_RTS_B/FTM0_CH0/FTM2_FLT0/EWM_OUT_B/SWD_DIO)
SWD_DIO_TGTMCU_BUF: J12.1 U10.2(2B) U12.4(B)
TC_EXTAL_TP: TP9.1(PIN1) U5.10(EXTAL32)
TC_SDA_USB_ID_TP: J6.4(P4) TP7.1(PIN1)
TC_XTAL_TP: TP10.1(PIN1) U5.9(XTAL32)
THER_A: C21.1 R45.2 R47.2 RT1.1
THER_B: C21.2 R44.1 R46.2 RT1.2
TP_2102_A: TP3.1(PIN1) U3.3(A2)
TP_2102_B: TP2.1(PIN1) U3.6(B2)
UART0_RX_TGTMCU: J1.6(B3) R24.2 R54.2
UART0_TX_TGTMCU: R38.2 R55.1
UART1_RX_TGTMCU_BUF: R24.1 U7.4(B)
UART1_RX_TGTMCU_R: U5.25(PTC4/SPI0_PCS0/UART1_TX/FTM0_CH3/CMP1_OUT/LLWU_P8) U7.3(A)
UART1_TX_TGTMCU_BUF: R38.1 U10.1(1B)
UART1_TX_TGTMCU_R: U5.24(CMP1_IN1/PTC3/SPI0_PCS1/UART1_RX/FTM0_CH2/I2S0_TX_BCLK/LLWU_P7) U10.6(1A)
V_TGTMCU: C7.1 C23.1 R2.1 R11.1 SH1.1 U2.6(VCCB) U3.8(VCCB) U7.6(VCCB) U10.8(VCCB) U12.6(VCCB)
VREFH: C29.1 C42.1 C43.1 L9.1 R53.1 U13.10(VREFH)
VREFL: C29.2 C42.2 C43.2 L10.1 U13.11(VREFL)
VTRG_EN: R29.2 R30.1 R34.2 U11.3(ENABLE)
VTRG_FAULT_B: R35.2 U5.32(PTD7/CMT_IRO/UART0_TX/FTM0_CH7/FTM0_FLT1) U11.4(F\A\U\L\T\)
N20314503: R42.1 R64.1 U8.16(RST)
N20662233: C19.2 U11.5(CSLEW)
N20923344: D4.2(COMMON_A) R88.2
N21117280: C24.2 QZ1.2 R52.1 U13.24(EXTAL0/PTA18/FTM0_FLT2/FTM_CLKIN0)
N21117910: C20.2 QZ1.1 R52.2 U13.25(XTAL0/PTA19/FTM0_FLT0/LPTMR0_ALT1/FTM1_FLT0/FTM_CLKIN1)
N21118289: R55.2 U13.32(PTB17/UART0_TX/FTM_CLKIN1/EWM_OUT_B)
N21118309: R54.1 U13.31(PTB16/UART0_RX/FTM_CLKIN2/EWM_IN)
N21120929: R58.2 U13.41(PTD0/LLWU_P12/SPI0_PCS0/SS_B/UART0_CTS_B/FTM0_CH0/UART1_RX)
N21120946: R59.1 U13.42(ADC0_SE2/PTD1/SPI0_SCK/UART0_RTS_B/FTM0_CH1/UART1_TX)
N21121221: R66.2 U13.30(ADC1_SE2/ADC1_DP2/PTB3/UART0_CTS_B/I2C0_SDA/FTM0_FLT0)
N21128407: R65.1 U13.29(ADC0_SE10/ADC1_SE10/ADC1_DM2/PTB2/I2C0_SCL/FTM0_FLT1/UART0_RTS_B/FTM0_FLT3)
N21239718: C51.2 R48.1

Pads without a net: J3 2; J9 6 7 8 9; J10 7 9; U8 15

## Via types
v1: diameter 0.508, hole 0.254, TOP to BOTTOM, 516 vias
v2: diameter 0.61, hole 0.305, TOP to BOTTOM, 52 vias

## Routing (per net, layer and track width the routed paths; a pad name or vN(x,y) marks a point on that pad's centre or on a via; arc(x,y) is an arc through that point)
GND: length 200.6
  TOP w0.203: v1(37.36,24.47) 37.36,25.03 U3.4
  TOP w0.254: U10.4 v1(27.9,35.59) ; U12.2 v1(31.46,37.87) ; U7.2 v1(26.63,37.87) ; v2(18.5,33.81) 17.3,33.81 U5.8 ; U9.2 v1(14.5,27.2) ; v1(29.17,34.82) 28.5,34.82 U10.3 ; U5.2 19.77,35.58 v2(19.77,35.08) ; U2.2 v1(31.46,34.32)
  TOP w0.305: v1(65.62,21.68) 65.62,21.35 U13.2 ; U8.5 57.48,40.65 59.02,42.19 v1(59.65,42.19) ; 53.24,38.65 U8.13 ; U8.12 53.37,39.15 ; U13.23 55.07,21.49 v1(54.76,21.49) ; v1(59.65,40.67) 59.04,40.67 57.96,39.65 U8.3
  TOP w0.381: v2(5.42,33.55) 5.26,33.72 J6.5 ; v1(19.77,24.09) Y1.2 v1(19.77,27.14) ; C6.2 v1(20.28,28.47) ; C9.2 v1(19.27,28.47)
  TOP w0.508: C23.2 v1(41.11,28.47) ; C4.2 v1(61.43,38.38) ; C2.2 v1(7.58,47.02) ; R43.2 v1(50.25,41.17) ; 8.28,32.79 v2(8.28,31.84) ; 8.28,32.79 L1.2 ; 8.28,32.79 v2(8.28,33.68) 8.28,34.57 U6.2 ; C44.2 v1(36.79,39.65) ; J9.5 78.07,37.11 ; C10.2 v2(16.79,39.84) ; R31.2 v1(56.86,44.73) ; 41.97,2.57 J3.14 ; J3.14 44.31,2.57 ; J3.14 43.14,3.73 ; J3.14 43.14,1.4 ; 25.32,50.83 J2.14 ; J2.14 27.66,50.83 ; J2.14 26.49,49.66 ; J2.14 26.49,51.99 ; J10.5 v2(4.79,25.43) ; v2(16.92,13.49) C41.2 v2(19.08,13.49) ; 16.67,21.62 v2(18.38,21.62) ; 16.67,21.62 v2(15.01,21.62) ; 16.67,21.62 U17.1 ; U11.2 C16.2 v2(12.09,40.92) ; v1(61.43,39.9) C3.2 ; v1(54.76,21.49) 54.23,22.02 C31.2 ; J3.12 41.77,2.57 ; J3.12 40.6,1.4 ; J3.12 40.6,3.73 ; J3.12 39.43,2.57 ; C7.2 v1(39.59,28.47) ; 18.04,6.29 J24.3 ; J24.3 16.99,8.35 ; J24.3 18.04,10.41 ; J24.3 19.1,8.35 ; C32.2 66.15,22.21 v1(65.62,21.68) ; J27.2 41.69,11.2 ; J27.2 40.6,12.29 ; J27.2 39.51,11.2 ; J27.2 40.6,10.11 ; v2(24.03,4.09) C40.2 v2(26.19,4.09) ; C5.2 v1(61.18,37.62) ; C516.2 v1(39.33,39.65) ; C13.2 v1(53.81,44.73) ; v2(26.7,17.04) R48.2 v2(24.54,17.04) ; R6.2 v1(23.2,28.35) ; SW2.2 v1(78.96,49.56) ; v2(8.22,36.98) 8.22,36.11 U4.2 ; C507.2 v1(34.25,39.65) ; SW3.2 v1(78.89,8.41) ; TP16.1 3.34,25.43 ; TP16.1 2.25,26.52 ; TP16.1 1.16,25.43 ; TP16.1 2.25,24.33 ; C34.2 v2(48.22,27.71) ; R13.2 v1(36.54,34.32) ; C15.2 v2(17.93,42.25) ; v2(3.71,26.7) C18.2 v1(5.3,26.7) J10.3 ; C11.2 v2(13.74,37.81) ; C24.1 v1(50.76,23.14) ; L8.2 51.52,28.98 v2(51.52,27.71) ; SW1.1 v2(4.53,49.56) ; R16.2 v1(31.46,37.87) ; J24.2 24.04,9.41 ; J24.2 25.1,7.35 ; J24.2 24.04,5.29 ; J24.2 22.99,7.35 ; C50.2 v2(48.73,11.9) ; C1.2 v2(13.23,36.28) ; C52.2 v2(47.21,11.9) ; C12.2 v2(17.55,40.6) ; C505.2 v1(41.87,39.4) ; C33.2 v2(50,27.71) ; C14.2 v1(53.81,34.57) ; v2(34.44,9.42) C53.2 v2(36.6,9.42) ; R42.2 v1(57.75,34.32) ; C522.2 v1(31.71,39.65) ; R44.2 v1(77.18,29.49) ; C35.2 v1(65.87,25.3) ; C22.2 v1(66.76,24.41) ; R39.2 v1(36.54,37.87) ; U1.2 v2(9.23,37.87) ; C55.2 v1(75.4,10.95) ; R30.2 v1(15.2,41.68) ; C17.2 v1(38.06,28.47) ; C20.1 v1(50.76,15.52) ; C56.2 v1(75.4,47.02) ; R7.2 v1(24.47,38.25) ; J9.3 78.07,35.84 ; C54.2 v2(45.68,11.9) ; C8.2 v1(11.39,28.47)
  GND w0.381: 26.49,50.82 J2.14
  GND w0.508: J2.14 26.49,51.99 ; J2.14 27.66,50.83 ; J2.14 25.32,50.83 ; J3.14 44.31,2.57 ; J3.14 43.14,3.73 ; J3.14 41.97,2.57 ; J3.14 43.14,1.4 ; 39.51,11.2 J27.2 ; J27.2 41.69,11.2 ; J27.2 40.6,12.29 ; J27.2 40.6,10.11 ; J9.3 77.89,35.84 ; J3.12 40.6,3.73 ; J3.12 41.77,2.57 ; J3.12 40.6,1.4 ; J3.12 39.43,2.57 ; J24.2 25.1,7.35 ; J24.2 24.04,5.29 ; J24.2 22.99,7.35 ; J24.2 24.04,9.41 ; J9.5 77.89,37.11 ; 16.99,8.35 J24.3 ; J24.3 18.04,6.29 ; J24.3 19.1,8.35 ; J24.3 18.04,10.41 ; 5.47,25.43 J10.5 ; 1.16,25.43 TP16.1 ; TP16.1 2.25,24.33 ; TP16.1 2.25,26.52 ; TP16.1 3.34,25.43 ; 5.47,26.7 J10.3
  INT_1 w0.508: J9.5 77.89,37.11 ; J24.3 18.04,10.41 ; J24.3 19.1,8.35 ; J24.3 18.04,6.29 ; J24.3 16.99,8.35 ; J2.14 27.66,50.83 ; 22.99,7.35 J24.2 ; J24.2 24.04,5.29 ; J24.2 24.04,9.41 ; J24.2 25.1,7.35 ; 40.6,10.11 J27.2 ; J27.2 39.51,11.2 ; J27.2 41.69,11.2 ; 1.16,25.43 TP16.1 ; TP16.1 2.25,26.52 ; TP16.1 2.25,24.33 ; J9.3 77.89,35.84 ; 39.43,2.57 J3.12 ; 5.47,25.43 J10.5 ; 5.47,26.7 J10.3
  vias: v1(0.85,47.08) v1(0.85,44.54) v1(0.85,42) v1(0.85,27.97) v1(0.85,25.43) v1(0.85,22.89) v1(0.85,20.35) v1(0.85,17.81) v1(0.85,15.27) v1(0.85,12.73) v1(0.85,10.19) v1(0.85,7.65) v1(0.98,5.11) v1(1.55,49.56) v1(2.37,2.57) v1(3.39,49.62) v1(3.39,47.08) v1(3.39,15.27) v1(3.39,12.73) v1(3.39,10.19) v1(3.39,7.65) v1(3.39,5.11) v1(4.28,1.23) v1(4.34,52.1) v1(5.93,47.08) v1(5.93,20.35) v1(5.93,17.81) v1(5.93,15.27) v1(5.93,12.73) v1(5.93,10.19) v1(5.93,7.65) v1(5.93,5.11) v1(5.93,2.57) v1(6.82,0.85) v1(6.95,52.48) v1(8.47,40.22) v1(8.47,20.35) v1(8.47,17.81) v1(8.47,15.27) v1(8.47,12.73) v1(8.47,10.19) v1(8.47,7.65) v1(8.47,5.11) v1(8.47,2.57) v1(9.36,0.85) v1(9.49,52.48) v1(11.01,37.68) v1(11.01,35.14) v1(11.01,32.6) v1(11.01,20.35) v1(11.01,17.81) v1(11.01,15.27) v1(11.01,12.73) v1(11.01,10.19) v1(11.01,7.65) v1(11.01,5.11) v1(11.01,2.57) v1(11.39,29.55) v1(11.39,24.92) v1(11.9,0.85) v1(13.55,40.22) v1(13.55,29.55) v1(13.55,22.89) v1(13.55,20.35) v1(13.55,17.81) v1(13.55,15.27) v1(13.55,12.73) v1(13.55,10.19) v1(16.09,40.22) v1(16.09,22.89) v1(16.09,12.73) v1(16.09,10.19) v1(16.34,52.48) v1(16.34,47.4) v1(16.34,44.86) v1(18.63,22.89) v1(18.63,12.73) v1(18.63,5.11) v1(18.76,0.85) v1(18.88,52.48) v1(18.88,44.86) v1(19.52,20.35) v1(19.52,17.81) v1(21.17,22.89) v1(21.17,5.11) v1(21.42,52.48) v1(21.42,44.86) v1(22.82,0.85) v1(23.71,25.43) v1(23.71,22.89) v1(23.71,12.73) v1(23.71,10.19) v1(23.96,52.48) v1(25.11,0.85) v1(26.25,27.97) v1(26.25,25.43) v1(26.25,22.89) v1(26.25,12.73) v1(26.25,10.19) v1(26.5,52.48) v1(26.5,44.86) v1(26.5,42.32) v1(26.63,35.59) v1(27.9,0.85) v1(28.41,46.63) v1(28.41,44.48) v1(28.79,30.51) v1(28.79,22.89) v1(29.04,52.48) v1(29.68,46.63) v1(29.68,44.48) v1(31.33,30.51) v1(31.33,27.97) v1(31.33,25.43) v1(31.33,22.89) v1(31.33,19.33) v1(31.33,16.03) v1(31.33,12.73) v1(31.33,10.19) v1(31.58,52.48) v1(32.98,7.14) v1(32.98,0.85) v1(33.87,22.89) v1(33.87,12.73) v1(34.12,52.48) v1(34.32,16.03) v1(35.52,44.48) v1(35.52,7.14) v1(36.54,31.78) v1(36.54,19.33) v1(36.54,16.03) v1(36.66,52.48) v1(38.06,44.48) v1(38.82,35.78) v1(38.82,31.78) v1(39.2,52.48) v1(39.27,16.03) v1(39.33,10.19) v1(39.59,19.33) v1(40.6,44.48) v1(40.6,8.15) v1(40.6,7.14) v1(41.62,35.78) v1(41.62,31.78) v1(41.62,26.19) v1(41.62,23.65) v1(42.63,37.87) v1(43.14,16.03) v1(43.14,6.63) v1(43.4,33.55) v1(44.16,34.95) v1(44.16,31.78) v1(44.41,3.39) v1(44.92,8.15) v1(45.36,39.33) v1(45.68,28.73) v1(45.68,26.19) v1(45.68,23.65) v1(45.68,21.11) v1(45.68,18.57) v1(45.68,16.03) v1(45.68,6.63) v1(46.95,33.11) v1(47.21,8.15) v1(47.21,5.11) v1(48.22,20.09) v1(49.24,2.06) v1(49.75,7.65) v1(50,34.32) v1(50,31.78) v1(50.76,26.19) v1(50.76,20.09) v1(50.76,18.57) v1(50.76,10.95) v1(50.76,6.63) v1(52.1,2.06) v1(52.67,10.95) v1(53.17,17.04) v1(54.06,26.19) v1(54.76,19.39) v1(56.98,12.03) v1(58.76,17.04) v1(61.18,8.28) v1(62.26,2.06) v1(62.45,39.9) v1(62.89,10.38) v1(64.22,6.63) v1(64.22,3.84) v1(65.24,52.48) v1(65.75,28.35) v1(65.75,0.85) v1(71.08,52.48) v1(71.59,47.27) v1(71.59,44.73) v1(71.59,42.19) v1(71.59,39.65) v1(71.59,37.11) v1(71.59,32.03) v1(71.59,29.49) v1(71.59,26.95) v1(71.59,24.28) v1(71.59,21.74) v1(71.59,19.2) v1(71.59,11.01) v1(71.59,8.47) v1(71.59,5.93) v1(71.59,0.85) v1(73.62,52.48) v1(74.13,42.19) v1(74.13,32.03) v1(74.13,29.49) v1(74.13,26.95) v1(74.13,24.28) v1(74.13,21.74) v1(74.13,19.2) v1(74.13,5.93) v1(74.13,3.39) v1(74.13,0.85) v1(76.16,52.35) v1(76.67,47.27) v1(76.67,44.73) v1(76.67,42.19) v1(76.67,32.03) v1(76.67,19.2) v1(76.67,11.01) v1(76.67,5.93) v1(76.67,3.39) v1(77.11,23.39) v1(77.37,1.42) v1(78.57,51.08) v1(79.72,49.56) v1(79.78,3.84) v1(80.42,47.02) v1(80.42,44.48) v1(80.42,41.94) v1(80.42,39.4) v1(80.42,36.86) v1(80.42,34.32) v1(80.42,31.78) v1(80.42,29.24) v1(80.42,26.7) v1(80.42,24.16) v1(80.42,21.62) v1(80.42,19.08) v1(80.42,16.54) v1(80.42,14) v1(80.42,11.46) v1(80.42,8.92) v1(80.42,6.38) v2(19.77,33.81) v2(19.77,32.54) v2(21.04,33.81)
P3V3: length 51.8
  TOP w0.305: C14.1 54.83,35.34 U8.14 ; C4.1 59.38,38.65 U8.1
  TOP w0.508: R88.1 v1(79.02,15.01) ; R1.1 v1(75.4,45.49) ; v2(26.19,2.57) C40.1 v2(24.03,2.57) ; R32.1 v1(57.87,45.49) ; C5.1 v1(59.65,37.62) C4.1 ; R40.1 v1(48.73,41.17) ; v1(58.45,10.82) R50.1 ; R15.1 v1(59.65,43.97) ; C14.1 v1(54.83,34.57) ; R45.1 v1(77.18,21.87) ; R75.1 v1(75.4,12.47) ; R9.1 v1(61.43,41.43) ; R61.1 35.52,18.06 ; R63.1 40.6,18.06 ; R49.1 v1(55.91,10.82)
  TOP w0.889: J20.1 J18.2 J19.1 28.64,18.06 D11.C
  BOTTOM w0.508: J20.1 44.23,18.06 ; J20.1 42.05,18.06 ; J20.1 43.14,16.97 ; 30.44,1.4 J3.4 ; J3.4 30.44,3.73 ; J3.4 29.27,2.57 ; J3.4 31.61,2.57 ; J3.8 36.69,2.57 ; J3.8 35.52,1.4 ; J3.8 35.52,3.73 ; J3.8 34.35,2.57 ; 31.89,18.06 J19.1 ; J19.1 34.07,18.06 ; J19.1 32.98,16.97
P3V3_KV10: length 54.8
  TOP w0.305: v1(66.32,20.98) 65.95,20.98 U13.1 ; U13.22 55.52,21.74 v1(55.52,22.12)
  TOP w0.508: C34.1 50,30.96 50,30.95 ; C31.1 54.93,22.72 v1(55.52,22.12) ; C32.1 66.85,21.51 v1(66.32,20.98) ; 50,30.95 C33.1 ; 50,30.95 51.56,30.95 L3.2 ; R63.2 40.6,20.09 41.11,20.6 J20.2 ; v2(68.16,20.98) 78.89,20.98 79.59,21.68 79.59,33.55 78.57,34.57 J9.1
  TOP w0.889: C34.1 45,30.96 43.14,29.11 J20.2
  BOTTOM w0.508: 43.14,21.69 J20.2 44.23,20.6
P3V3_SDA: length 32.6
  TOP w0.203: U3.1 v1(38.06,27.46)
  TOP w0.254: v1(26.63,38.89) 26.63,38.57 26.83,38.37 U7.1 ; U10.7 v1(26.64,33.82) ; v1(31.46,35.01) 31.66,34.82 U2.1 ; v1(16.54,35.14) 16.67,35.14 U5.7 ; U12.1 31.66,38.37 31.46,38.57 v1(31.46,38.89) ; C8.1 11.9,27.2 U9.5 ; U5.1 18.69,37.36 v2(18.69,37.93) ; U5.11 17.53,32.64 v1(16.98,32.09)
  TOP w0.508: C15.1 v2(20.47,39.71) ; R14.1 v1(35.78,24.16) ; C18.1 v2(3.71,27.71) ; R17.1 v2(3.26,42) ; J10.1 7.07,28.09 v1(7.07,28.98) R21.1 ; R37.1 v1(36.54,38.89) ; R12.1 v1(36.54,35.33) ; C10.1 v2(18.69,37.93) ; R61.2 v1(35.52,20.35) ; R35.1 v2(14.5,44.48) ; R27.2 v1(16.22,29.49) ; R23.1 v1(30.7,39.65) ; R26.1 v1(16.22,24.92) ; C12.1 v2(19.46,38.7) ; R4.2 v1(39.33,22.89) ; R36.1 v2(11.71,35.78) ; C8.1 v1(11.39,25.93) ; C17.1 v1(38.06,27.46)
  BOTTOM w0.508: J18.1 38.06,21.69 ; J18.1 38.06,19.51 ; J18.1 36.97,20.6 ; J18.1 39.15,20.6 ; 6.95,28.83 J10.1 5.47,27.97
P3V3_VREG: length 18.1
  TOP w0.889: J19.2 32.23,21.35 D11.A 27.9,21.36 C51.1 23.84,21.36 22.87,20.4 U17.4 v2(21.04,19.33) U17.2
P5V0_SDA_USB_CONN_VBUS: length 5.4
  TOP w0.381: J6.1 5.39,36.32 v1(5.49,36.41) 5.74,36.66 5.74,37.49 6.12,37.87 U1.1
  TOP w0.508: L2.1 6.88,37.87
P5V_OPT_VR: length 5.6
  TOP w0.889: 35.52,11.38 37.89,11.38 J27.3 ; 35.52,11.38 D13.A ; 35.52,11.38 C53.1
P5V_SDA: length 15.4
  TOP w0.254: U5.6 16.83,35.69 16.26,35.69 15.14,34.57 v2(15.14,34.38)
  TOP w0.508: R8.1 v1(23.71,39.01) ; R41.2 7.07,43.21 C19.1 9.7,43.21 U11.1 10.12,42.72 C16.1 v2(10.12,39.4) L2.2 ; R5.1 v1(23.96,29.11) ; C1.1 v2(15.14,34.38) ; R34.1 v1(13.68,41.68)
P5V_SDA_PSW: length 64.1
  TOP w0.508: R41.1 v2(6.82,45.62) 10.19,45.62 U11.6 ; D6.A v2(26.7,14.25)
  TOP w0.889: D6.A 27.98,11.38 D5.A
  INT_1 w0.508: v2(6.82,45.62) 4.28,43.08 4.28,39.4 2.95,38.06 2.95,26.44 3.96,25.43 3.96,16.28 5.99,14.25 v1(23.71,14.25) v2(26.7,14.25)
P5V_USB: length 25
  TOP w0.508: 39.33,8.15 39.33,3.84 J3.10 36.79,3.84 36.79,8.15
  TOP w0.889: D5.C 27.9,8.15 32.98,8.15 ; 39.33,8.15 32.98,8.15 ; 32.98,8.15 D13.C
VDDA: length 24.6
  TOP w0.203: U13.9 63.09,23.77 63.46,23.77 64.33,24.64 C30.1
  TOP w0.508: L3.1 53.52,30.76 C36.1 C39.1 58.17,30.76 L9.2 58.17,31.43 59.08,32.35 v1(60.03,32.35) 65.05,32.35 66.64,30.76 66.64,27.88 C30.1
VSSA: length 15.9
  TOP w0.203: C30.2 62.74,26.29 61.81,25.36 61.81,24.62 U13.12
  TOP w0.508: C30.2 63.61,27.05 63.02,27.65 v1(60.03,27.65) 59.08,27.65 58.17,28.56 L10.2 58.17,29.24 C39.2 C36.2 53.52,29.24 L8.1
ADC0_DM0: length 56.7
  TOP w0.152: J4.8 57.94,2.57 56.54,3.96 54.51,3.96 J4.3 ; R46.1 67.65,26.19 65.52,24.05 C35.1 63.97,23.39 63.42,23.39 U13.8 61.68,21.66 61.68,20.09 62.6,19.18 65.85,19.18 66.38,19.71 67.14,19.71 67.65,19.2 67.65,17.93 70.19,15.39 v1(70.19,12.85)
  INT_1 w0.152: v1(70.19,12.85) 68.29,12.85 61.68,6.25 54.51,6.25 J4.3
ADC0_DP0: length 58.7
  TOP w0.152: v1(70.7,13.36) 70.7,15.52 68.16,18.06 68.16,19.33 67.4,20.09 66.26,20.09 65.65,19.48 62.8,19.48 62.06,20.22 62.06,21.42 63.12,22.48 63.21,22.48 63.81,23.08 65.43,23.08 C22.1 66.4,23.16 68.41,25.17 R47.1 ; J4.1 52.1,3.84 54.13,3.84 55.4,2.57 J4.6
  INT_1 w0.152: J4.1 52.98,7.26 62.06,7.26 68.16,13.36 v1(70.7,13.36)
ADC0_SE5/PTE17: length 52.2
  TOP w0.152: v1(63.33,20.47) 63.33,20.48 U13.4 ; v1(35.52,42.89) 34.25,42.89 C507.1 R551.1
  INT_1 w0.152: v1(35.52,42.89) 36.6,43.97 44.67,43.97 45.17,43.46 51.14,43.46 52.67,41.94 56.48,41.94 58.76,39.65 59.91,39.65 60.67,38.89 61.68,38.89 62.19,38.38 62.19,25.81 63.53,24.47 63.53,20.66 v1(63.33,20.47)
ADC0_SE5_RC: length 2.9
  TOP w0.152: R551.2 34.25,48.15 J2.7
ADC0_SE6/PTE18: length 42.2
  TOP w0.152: v1(62.57,20.47) 62.62,20.47 U13.5 ; v1(43.14,42.89) 41.87,42.89 C505.1 R534.1
  INT_1 w0.152: v1(43.14,42.89) 43.33,42.7 50.63,42.7 52.16,41.17 55.97,41.17 58.89,38.25 59.78,38.25 60.16,37.87 60.16,37.11 61.43,35.84 61.43,24.54 62.06,23.9 62.06,20.98 v1(62.57,20.47)
ADC0_SE6_RC: length 2.9
  TOP w0.152: R534.2 41.87,48.15 J2.1
ADC0_SE7/PTE19: length 46.9
  TOP w0.152: R76.1 C44.1 36.79,42.89 v1(38.06,42.89) ; 63.56,22.12 62.67,21.23 v1(62.57,21.23)
  INT_1 w0.152: v1(38.06,42.89) 38.63,43.46 44.54,43.46 44.92,43.08 50.89,43.08 52.41,41.55 56.22,41.55 59.14,38.63 60.03,38.63 60.54,38.13 60.54,37.36 61.81,36.09 61.81,24.79 62.57,24.03 v1(62.57,21.23)
ADC0_SE7_RC: length 2.9
  TOP w0.152: R76.2 36.79,48.15 J2.5
ADC0_SE9/PTB1: length 42.2
  TOP w0.152: C516.1 40.27,42.9 40.6,42.57 v1(40.6,40.79) ; C516.1 39.33,42.89 ; C516.1 R549.1 ; U13.28 57.11,17.8 57.11,17.81 57.24,17.93 v1(57.75,17.93)
  INT_1 w0.152: v1(40.6,40.79) 46.19,40.79 47.84,39.14 49.11,39.14 49.62,38.63 53.05,38.63 56.86,34.82 56.86,26.76 57.37,26.25 57.37,18.31 v1(57.75,17.93)
ADC0_SE9_RC: length 2.9
  TOP w0.152: R549.2 39.33,48.15 J2.3
ADC1_SE4/PTE30: length 63.5
  TOP w0.152: v1(56.73,26.19) 56.74,26.19 U13.14 60.92,22 60.92,19.58 v1(62.57,17.93) ; v1(32.98,40.28) 32.98,42.51 32.6,42.89 31.71,42.89 C522.1 R555.1 ; J4.11 63.59,5.17 v1(63.59,10.82)
  INT_1 w0.152: v1(62.57,17.93) 62.57,11.84 v1(63.59,10.82) ; v1(56.73,26.19) 56.48,26.44 56.48,34.44 52.79,38.13 47.46,38.13 45.68,39.9 39.97,39.9 39.59,40.28 v1(32.98,40.28)
ADC1_SE4_RC: length 2.9
  TOP w0.152: R555.2 31.71,48.15 J2.9
AREF: length 60.2
  TOP w0.203: R53.2 v1(65.75,29.74) ; v1(25.23,45.62) 25.23,49.54 J2.16
  INT_1 w0.203: v1(25.23,45.62) 44.92,45.62 45.43,45.11 52.67,45.11 54.06,43.71 58.57,43.71 59.33,44.48 61.3,44.48 65.24,40.54 65.24,31.9 65.75,31.39 v1(65.75,29.74)
DC_JACK: length 2.2
  TOP w0.889: J24.1 D9.A
FXOS8700CQ_CRST: length 3.8
  TOP w0.152: U8.8 54.83,43.96 C13.1 v1(54.83,44.73)
FXOS8700CQ_I2C_SA0: length 6.4
  TOP w0.152: v1(55.84,46.32) R32.2 R31.1 55.84,43.4 55.33,42.89 U8.7
  BOTTOM w0.152: v1(55.84,46.32) R32.2
FXOS8700CQ_I2C_SA1: length 5.4
  TOP w0.152: R40.2 v1(50.25,40.16) R43.1 51.02,40.15 U8.10
  BOTTOM w0.152: v1(50.25,40.16) TP11.1
LEDRGB_BLUE: length 3.7
  TOP w0.152: D4.3 76.66,18.06 R73.1 v1(79.02,18.06)
  BOTTOM w0.152: R73.1 v1(79.02,18.06)
LEDRGB_GREEN: length 3.7
  TOP w0.152: v1(72.8,18.06) R74.1 75.16,18.06 D4.4
  BOTTOM w0.152: R74.1 v1(72.8,18.06)
LEDRGB_RED: length 3.7
  TOP w0.152: v1(72.8,14) R69.2 75.16,14 D4.1
  BOTTOM w0.152: R69.2 v1(72.8,14)
LVLRST_EN: length 3.1
  TOP w0.152: U3.5 38.06,23.39 R4.1 v1(36.47,22.89)
MMA8451_BYP: length 4.8
  TOP w0.152: U8.2 58.33,39.15 v1(59.65,39.14) C3.1
  BOTTOM w0.152: v1(59.65,39.14) TP4.1
Net_3: length 0
  GND w0.152: 72.49,19.32 72.49,19.3
P5-9V_VIN: length 19.9
  TOP w0.889: J3.16 47.97,2.57 48.73,3.33 C50.1 C52.1 C54.1 43.65,9.42 43.14,9.93 J27.1 42.3,12.04 D10.A
P5-9V_VIN_VR: length 26.8
  TOP w0.889: U17.3 17.18,17.03 18,16.22 18,15.84 ; D10.C D6.C 28.94,15.84 v2(22.76,15.84) 21.04,15.84 ; 18,15.84 C41.1 ; 18,15.84 21.04,15.84 ; D9.C 21.04,15.84
POWER_EN: length 11.1
  TOP w0.152: U5.31 21.42,37.23 v1(21.42,41.68) ; R29.1 v1(16.73,41.68)
  INT_1 w0.152: v1(21.42,41.68) v1(16.73,41.68)
PTA1/FTM2_CH0: length 46.5
  TOP w0.152: 57.62,22.48 60.16,19.94 60.16,18.95 60.57,18.54 60.57,12.83 61.18,12.22 v1(61.18,10.31)
  INT_1 w0.152: J3.3 31.97,6.63 41.36,6.63 44.54,9.8 54.7,9.8 55.21,10.31 v1(61.18,10.31)
PTA2/FTM2_CH1: length 46.7
  TOP w0.152: v1(60.26,12.12) 60.26,18.34 59.78,18.82 59.78,19.71 58.38,21.11 58.16,21.11 57.27,22 57.27,22.12
  INT_1 w0.152: v1(60.26,12.12) 60.26,12.09 59.5,11.33 55.71,11.33 54.7,10.31 44.28,10.31 41.62,7.65 30.44,7.65 J3.1
PTA4: length 89.5
  TOP w0.152: v1(72.86,45.49) R1.2 C56.1 73.62,49.56 SW2.1 ; U13.21 57.88,20.09 58.32,20.09 58.76,19.65 v1(58.76,18.95) ; v1(58.76,33.81) v1(72.86,33.81)
  INT_1 w0.152: v1(58.76,33.81) 58.76,33.3 58.25,32.79 58.25,27.2 58.76,26.7 v1(58.76,18.95) ; v1(72.86,33.81) v1(72.86,45.49) 66.64,45.49 64.99,47.14 64.99,51.33 63.84,52.48 40.84,52.48 J2.4
PTB0: length 71
  TOP w0.152: SW3.1 73.62,8.41 C55.1 R75.2 72.22,12.47 71.72,12.98 71.72,15.9 v1(70.7,16.92) ; v1(47.59,40.67) 47.59,45.05 J1.11 J1.10 ; v1(59.78,17.93) 59.27,18.44 57.05,18.44 U13.27
  INT_1 w0.152: v1(47.59,40.67) 48.09,40.16 49.49,40.16 50,39.65 54.95,39.65 59.78,34.82 59.78,33.3 59.02,32.54 59.02,27.46 59.78,26.7 v1(59.78,17.93)
  BOTTOM w0.152: v1(59.78,17.93) 60.79,16.92 v1(70.7,16.92)
PTB2: length 98.6
  TOP w0.152: J2.20 20.14,49.56 22.68,49.56 J2.15 23.96,48.27 v1(23.96,40.79) ; U8.9 52.75,40.65 51.46,41.94 48.6,41.94 48.22,41.55 v1(48.22,38.63) v1(48.22,36.09) ; J4.12 62.13,3.96 59.59,3.96 J4.7 ; R50.2 v1(58.45,7.77) 57.94,7.26 55.08,7.26 53.43,8.92 53.43,12.6 52.67,13.36 v1(52.67,14.12) R65.2
  INT_1 w0.152: v1(48.22,38.63) 47.71,38.63 46.06,40.28 40.35,40.28 39.84,40.79 v1(23.96,40.79) ; v1(48.22,36.09) 51.4,36.09 52.41,35.08 52.41,18.19 52.67,17.93 v1(52.67,14.12)
  BOTTOM w0.152: v1(58.45,7.77) J4.7
PTB3: length 90.8
  TOP w0.152: v1(51.02,39.14) 51.52,39.65 U8.11 ; J4.10 60.48,2.57 59.08,3.96 57.05,3.96 J4.5 ; v1(29.04,41.3) 29.04,48.27 J2.11 ; R49.2 v1(55.91,7.77) 55.46,7.77 53.81,9.42 53.81,12.6 54.68,13.47 R66.1 v1(55.21,15.14)
  INT_1 w0.152: v1(55.21,15.14) 55.97,15.14 58.25,17.42 58.25,18.69 57.75,19.2 57.75,26.44 57.24,26.95 57.24,35.08 53.17,39.14 v1(51.02,39.14) 49.75,39.14 49.24,39.65 47.84,39.65 46.19,41.3 v1(29.04,41.3) ; J2.11 27.64,49.68 22.56,49.68 J2.18
  BOTTOM w0.152: v1(55.91,7.77) J4.5
PTC0: length 20.8
  TOP w0.152: v1(59.14,6.76) 59.14,10.95 57.62,12.47 57.62,14.77 U13.33
  INT_1 w0.152: v1(59.14,6.76) 53.17,6.76 52.16,5.74 52.16,3.9 J4.2
PTC1/FTM0_CH0: length 22.8
  TOP w0.152: U13.34 58,14.44 58,12.6 59.65,10.95 v1(59.65,8.79)
  INT_1 w0.152: v1(59.65,8.79) 55.59,8.79 55.08,8.28 48.86,8.28 J3.15
PTC2/FTM0_CH1: length 25.2
  TOP w0.152: U13.35 58.38,14.12 58.38,12.73 60.16,10.95 v1(60.16,9.3)
  INT_1 w0.152: v1(60.16,9.3) 55.46,9.3 54.95,8.79 46.82,8.79 J3.13
PTC3/FTM0_CH2: length 27.7
  TOP w0.152: v1(60.67,9.8) 60.67,10.95 58.76,12.85 58.76,13.79 U13.36
  INT_1 w0.152: v1(60.67,9.8) 55.33,9.8 54.83,9.3 44.79,9.3 J3.11
PTC4/FTM0_CH3: length 31.5
  TOP w0.152: v1(60.16,8.28) 61.68,9.8 61.68,12.22 62.06,12.6 62.06,13.79 U13.37
  INT_1 w0.152: J3.9 39.14,4.03 47.02,4.03 50.76,7.77 55.21,7.77 55.71,8.28 v1(60.16,8.28)
PTC5: length 90.2
  TOP w0.152: v1(61.18,17.42) 61.18,15.39 U13.38 62.45,14.12 62.45,12.34 62.19,12.09 62.19,6.31 J4.9 ; J2.12 27.77,49.57 v1(27.77,41.81)
  INT_1 w0.152: J2.12 27.89,51.97 20.79,51.97 20.15,51.33 20.15,49.54 J2.17 ; v1(61.18,17.42) 60.79,17.81 60.79,23.27 60.29,23.77 60.29,26.7 59.4,27.58 59.4,32.41 60.29,33.3 60.29,34.95 55.21,40.03 51.78,40.03 51.14,40.67 48.48,40.67 47.97,41.17 46.95,41.17 46.32,41.81 v1(27.77,41.81)
PTC6: length 80.2
  TOP w0.127: U13.39 62.95,14.31 62.95,12.73 v1(63.08,12.6)
  TOP w0.152: v1(26.5,46.13) 26.5,48.27 J2.13 ; v1(66.89,16.41) R67.2 ; v1(63.08,12.6) R60.2
  INT_1 w0.152: v1(63.08,12.6) 63.78,12.6 66.89,15.71 v1(66.89,16.41) 66.89,18.44 67.4,18.95 67.4,25.43 66.26,26.57 66.26,31.52 65.75,32.03 65.75,40.92 61.68,44.98 59.21,44.98 58.38,44.16 54.64,44.16 54.32,44.48 54.32,44.98 53.68,45.62 45.55,45.62 45.05,46.13 v1(26.5,46.13)
PTC6/I2C0_SCL: length 44.1
  TOP w0.152: v1(66.76,40.67) 60.41,40.67 R9.2 59.02,41.43 57.74,40.15 U8.4 ; v1(64.86,10.82) R60.1
  INT_1 w0.152: v1(66.76,40.67) 66.76,26.7 67.91,25.55 67.91,22.12 68.8,21.23 68.8,19.71 67.4,18.31 67.4,15.58 64.86,13.04 v1(64.86,10.82)
PTC6/SPI0_SOUT: length 69.5
  TOP w0.152: v1(35.52,46.63) 35.52,49.42 J2.8 ; v1(68.67,14.63) R67.1
  INT_1 w0.152: v1(35.52,46.63) 53.94,46.63 54.83,45.75 56.73,45.75 57.62,46.63 62.45,46.63 66.26,42.82 66.89,42.82 68.29,41.43 68.29,27.08 69.43,25.93 69.43,22.5 70.32,21.62 70.32,18.44 68.92,17.04 68.92,14.88 v1(68.67,14.63)
PTC7: length 66.4
  TOP w0.127: R62.1 64.33,12.11 63.33,13.11 63.33,14.64 U13.40
  TOP w0.152: J1.15 45.81,48.22 v1(45.81,46.13) ; v1(65.62,11.58) R62.1
  INT_1 w0.152: v1(65.62,11.58) 65.62,13.17 67.91,15.46 67.91,18.19 69.3,19.58 69.3,21.36 68.41,22.25 68.41,25.68 67.27,26.82 67.27,40.92 62.06,46.13 57.75,46.13 56.86,45.24 54.7,45.24 53.81,46.13 v1(45.81,46.13) ; J1.16 J1.15
PTC7/I2C0_SDA: length 47.9
  TOP w0.152: v1(58.89,45.49) 58.89,44.98 R15.2 55.83,41.93 U8.6 ; v1(66.26,39.14) v1(63.21,39.14) ; v1(63.84,13.36) R62.2
  INT_1 w0.152: v1(66.26,39.14) 66.26,41.17 61.94,45.49 v1(58.89,45.49) ; v1(63.21,39.14) 63.21,26.06 64.48,24.79 64.48,16.54 65.11,15.9 65.11,15.39 63.84,14.12 v1(63.84,13.36)
PTD0: length 51.9
  TOP w0.152: J1.7 56.97,49.35 62.05,49.35 J1.2 64.99,49.36 64.99,43.97 v1(66.76,42.19) ; v1(66.38,12.34) R58.1
  INT_1 w0.152: v1(66.38,12.34) 66.38,13.3 68.41,15.33 68.41,18.06 69.81,19.46 69.81,21.49 68.92,22.38 68.92,25.81 67.78,26.95 67.78,41.17 v1(66.76,42.19)
PTD1: length 60.4
  TOP w0.152: v1(65.37,14.88) R59.2 ; v1(52.03,43.97) 52.03,46.95 J1.9 54.84,49.76 59.92,49.76 J1.4 ; v1(63.72,35.33) R64.2
  INT_1 w0.152: v1(52.03,43.97) 53.17,42.82 60.79,42.82 63.72,39.9 v1(63.72,35.33) 63.72,26.19 64.99,24.92 64.99,16.66 65.62,16.03 65.62,15.14 v1(65.37,14.88)
PTD2: length 54.1
  TOP w0.152: v1(64.6,15.65) 64.45,15.65 63.56,16.54 ; v1(43.01,44.48) 43.01,49.54 J2.2
  INT_1 w0.152: v1(43.01,44.48) 44.79,44.48 45.3,43.97 51.27,43.97 52.86,42.38 56.67,42.38 58.89,40.16 60.03,40.16 60.79,39.4 61.81,39.4 62.7,38.51 62.7,25.93 63.97,24.66 63.97,16.28 v1(64.6,15.65)
PTD3: length 88.1
  TOP w0.127: U13.44 64.65,16.15 64.86,16.15 66.62,14.4 R68.1
  TOP w0.152: v1(67.91,13.87) R68.1
  INT_1 w0.152: v1(67.91,13.87) 68.61,13.87 69.43,14.69 69.43,16.92 70.83,18.31 70.83,21.74 69.94,22.63 69.94,26.06 68.8,27.2 68.8,41.55 67.02,43.33 66.51,43.33 62.7,47.14 20.02,47.14 J2.19
PTD3/SPI0_SIN: length 66.2
  TOP w0.152: v1(66.13,15.65) R68.2 ; J2.10 32.98,49.42 v1(32.98,44.98)
  INT_1 w0.152: v1(32.98,44.98) 44.92,44.98 45.3,44.6 52.41,44.6 53.75,43.27 60.99,43.27 64.22,40.03 64.22,31.65 64.73,31.14 64.73,25.81 65.43,25.11 65.43,22.69 66.13,22 66.13,21.49 65.43,20.79 65.43,17.36 66.13,16.66 v1(66.13,15.65)
PTD4/FTM0_CH4: length 53.2
  TOP w0.152: U13.45 64.98,16.54 66,16.54 66.45,16.98 67.27,16.98 69.18,15.07 v1(69.18,11.84)
  INT_1 w0.152: v1(69.18,11.84) 64.8,7.45 64.8,2.18 63.97,1.36 37.36,1.36 36.79,1.93 36.79,3.84 J3.7
PTD5/FTM0_CH5: length 57.1
  TOP w0.152: U13.46 65.3,16.92 65.75,16.92 66.19,17.36 67.59,17.36 69.68,15.27 v1(69.68,11.33)
  INT_1 w0.152: J3.5 34.19,3.9 34.19,1.93 35.14,0.98 64.29,0.98 65.24,1.93 65.24,6.88 v1(69.68,11.33)
PTD6: length 81.3
  TOP w0.152: J2.6 35.51,51.97 30.82,51.97 30.31,51.46 v1(30.31,42.32) ; v1(63.33,18.69) 64.23,18.69 U13.47 ; R69.1 73.37,15.01 69.81,18.57 v1(69.81,18.69)
  INT_1 w0.152: v1(30.31,42.32) 50.51,42.32 52.03,40.79 55.71,40.79 61.05,35.46 61.05,24.28 61.68,23.65 61.68,20.35 v1(63.33,18.69)
  BOTTOM w0.152: v1(69.81,18.69) v1(63.33,18.69)
